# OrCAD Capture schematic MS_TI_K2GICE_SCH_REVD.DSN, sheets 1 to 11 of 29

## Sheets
1 P01_Title Page: title: TABLE OF CONTENTS; rev: D; note: MS_TI_K2GICE_SCH_REVD
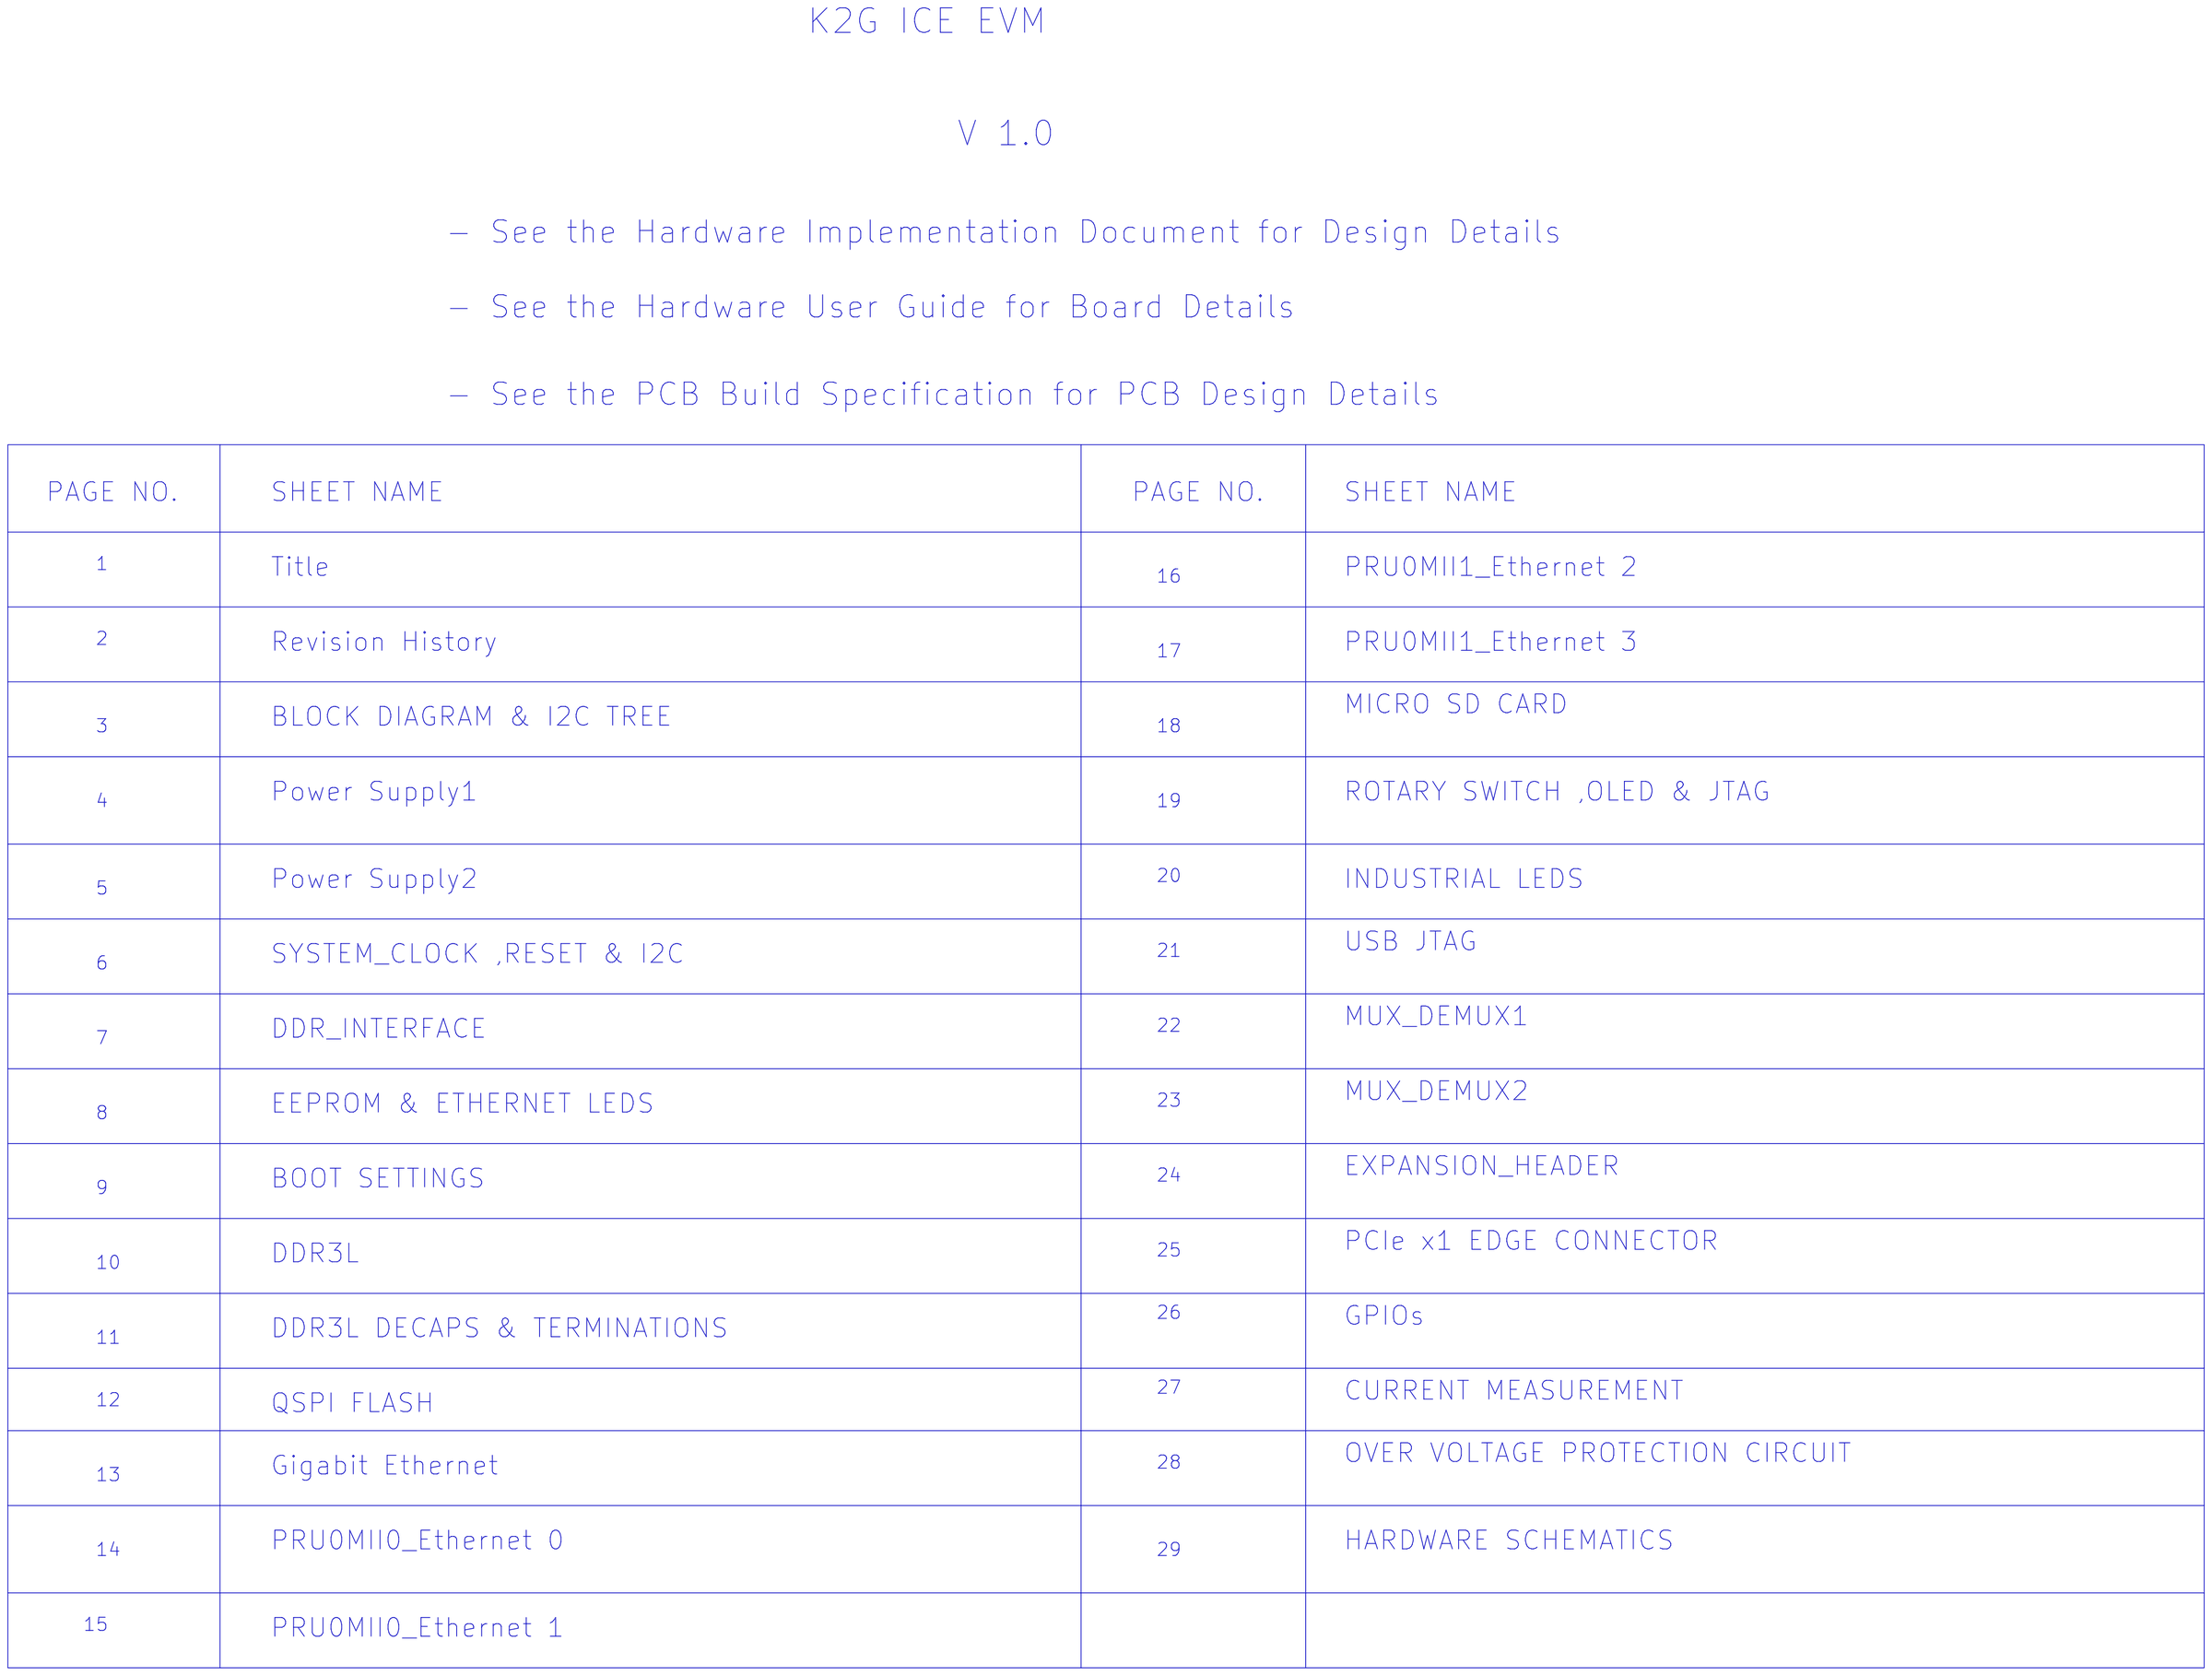
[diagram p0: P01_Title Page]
2 P02_Revision History: title: REVISION HISTORY
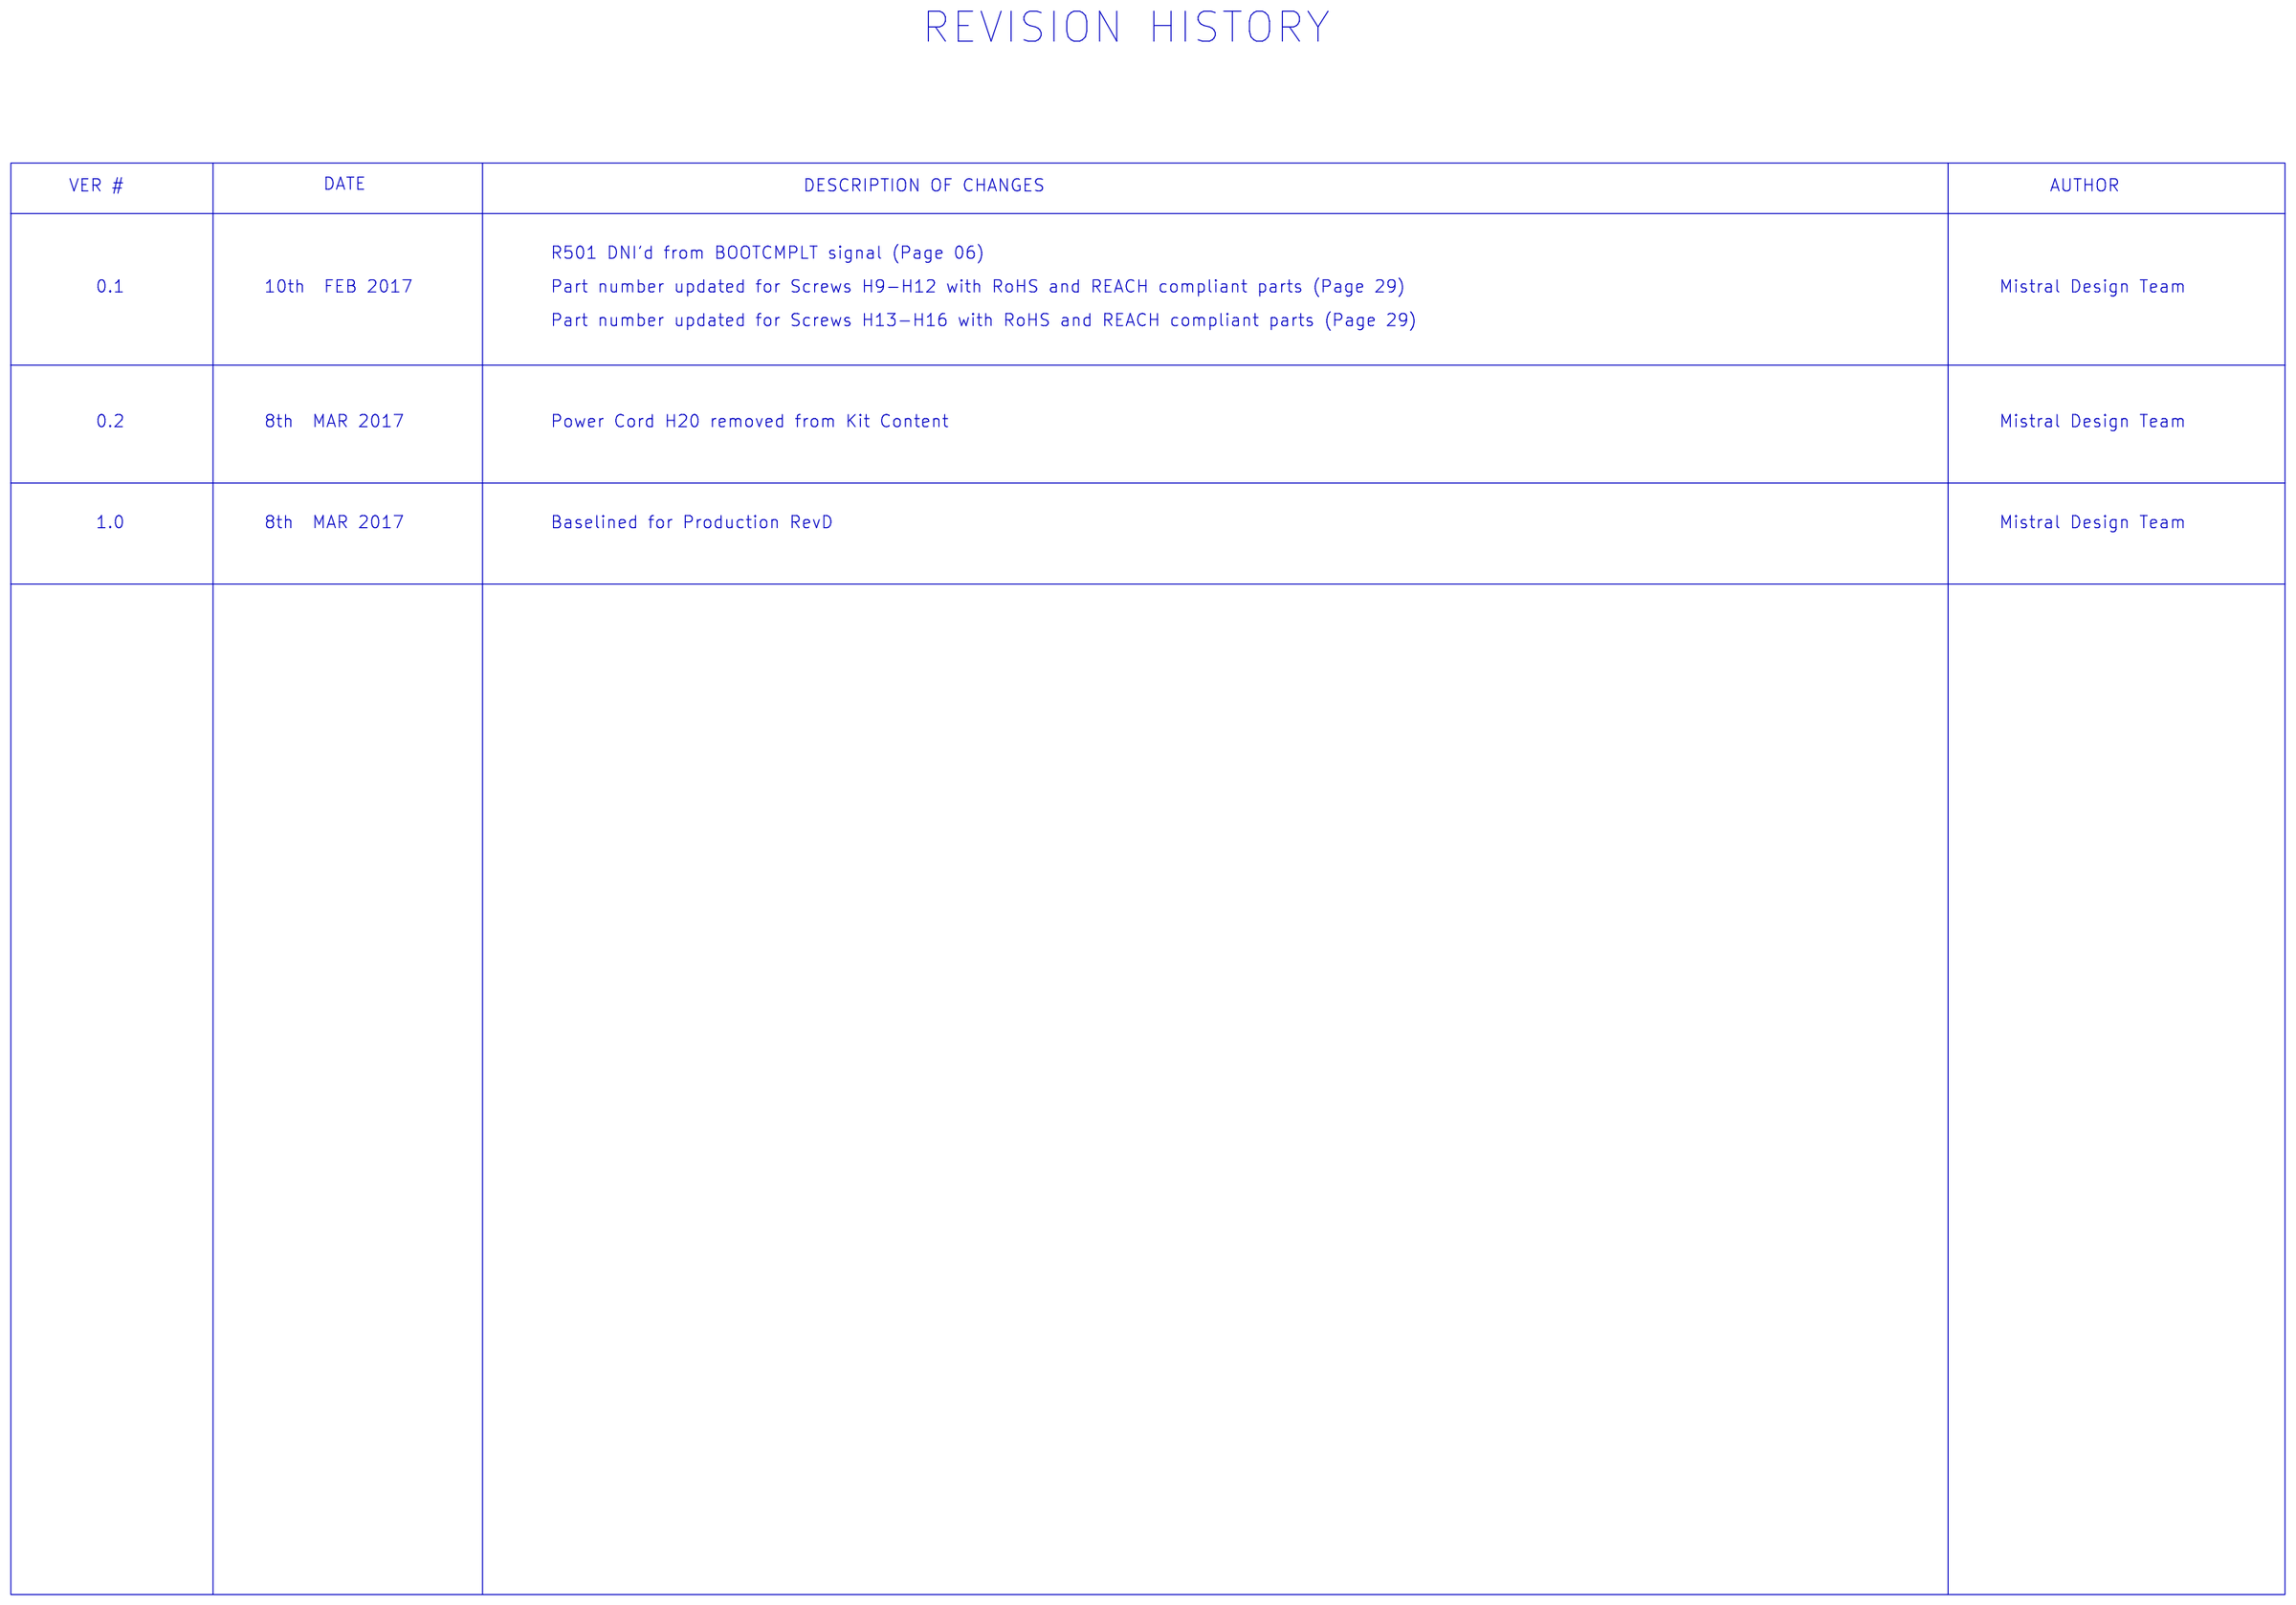
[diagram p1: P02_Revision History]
3 P03_BLOCK DIAGRAM & I2C TREE: title: BLOCK DIAGRAM & I2C TREE
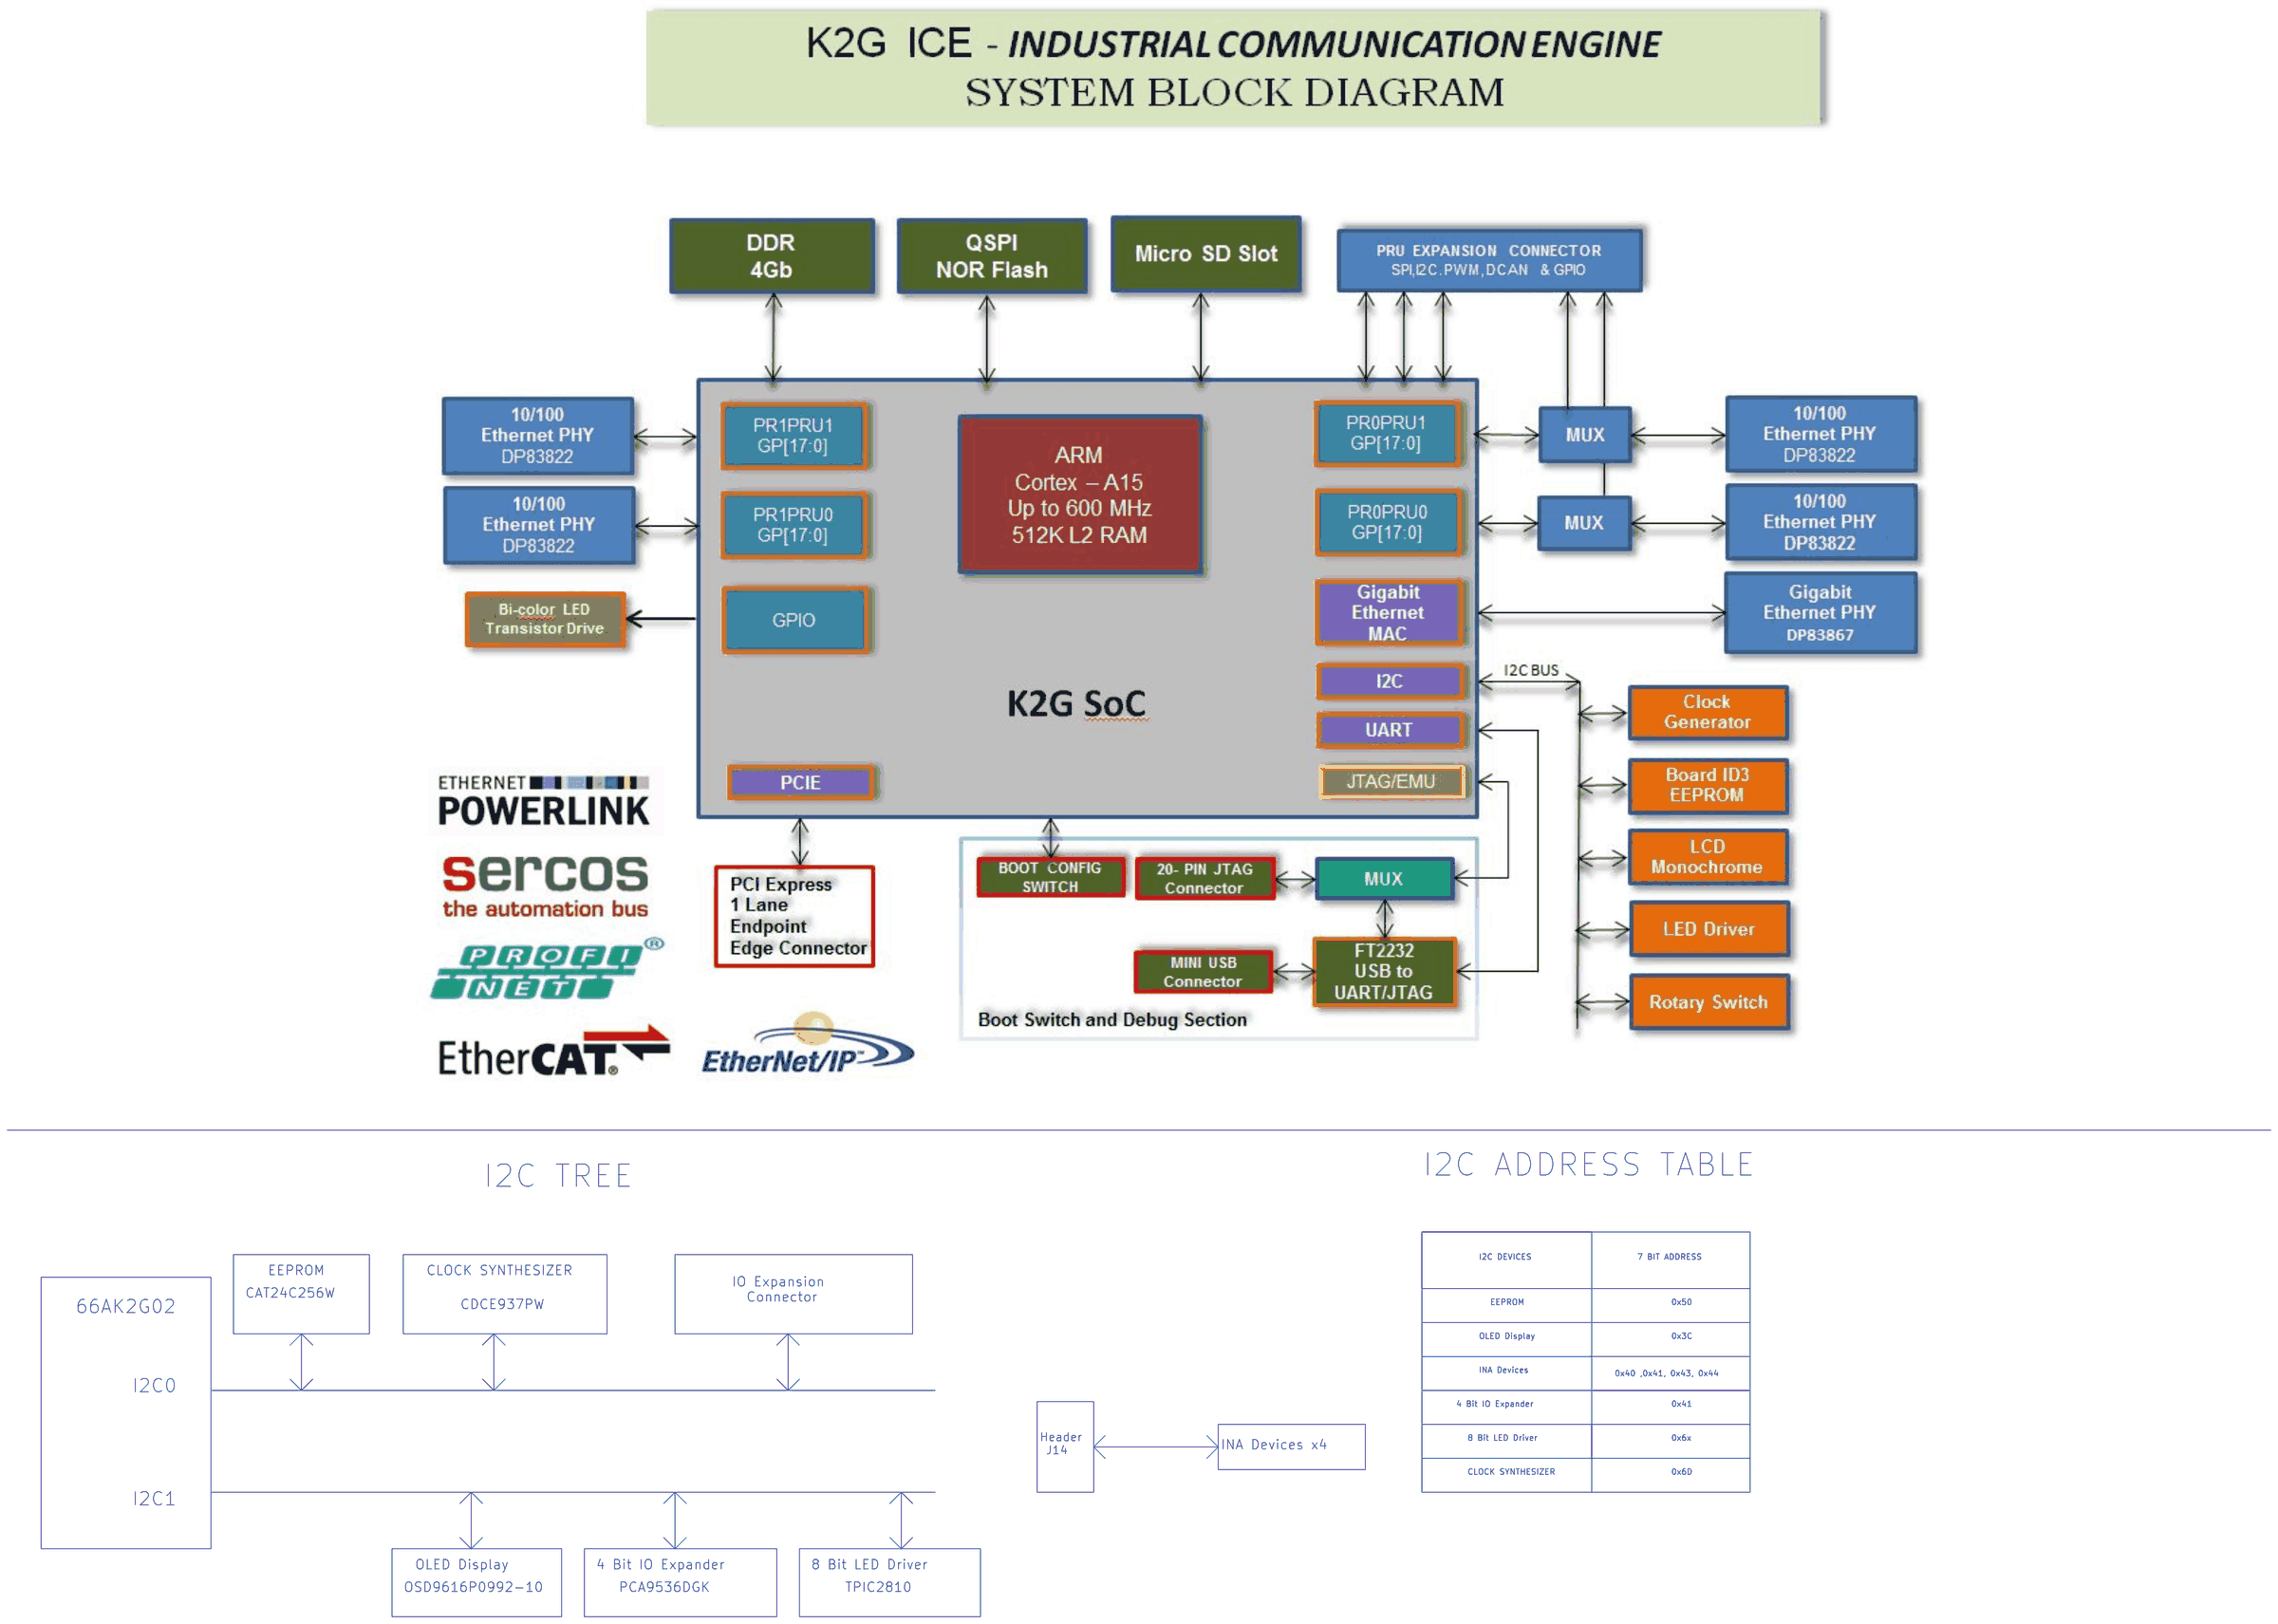
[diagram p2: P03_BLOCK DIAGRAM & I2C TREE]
4 P04_K2G_PowerSupply1: size C; title: POWER SUPPLY 1
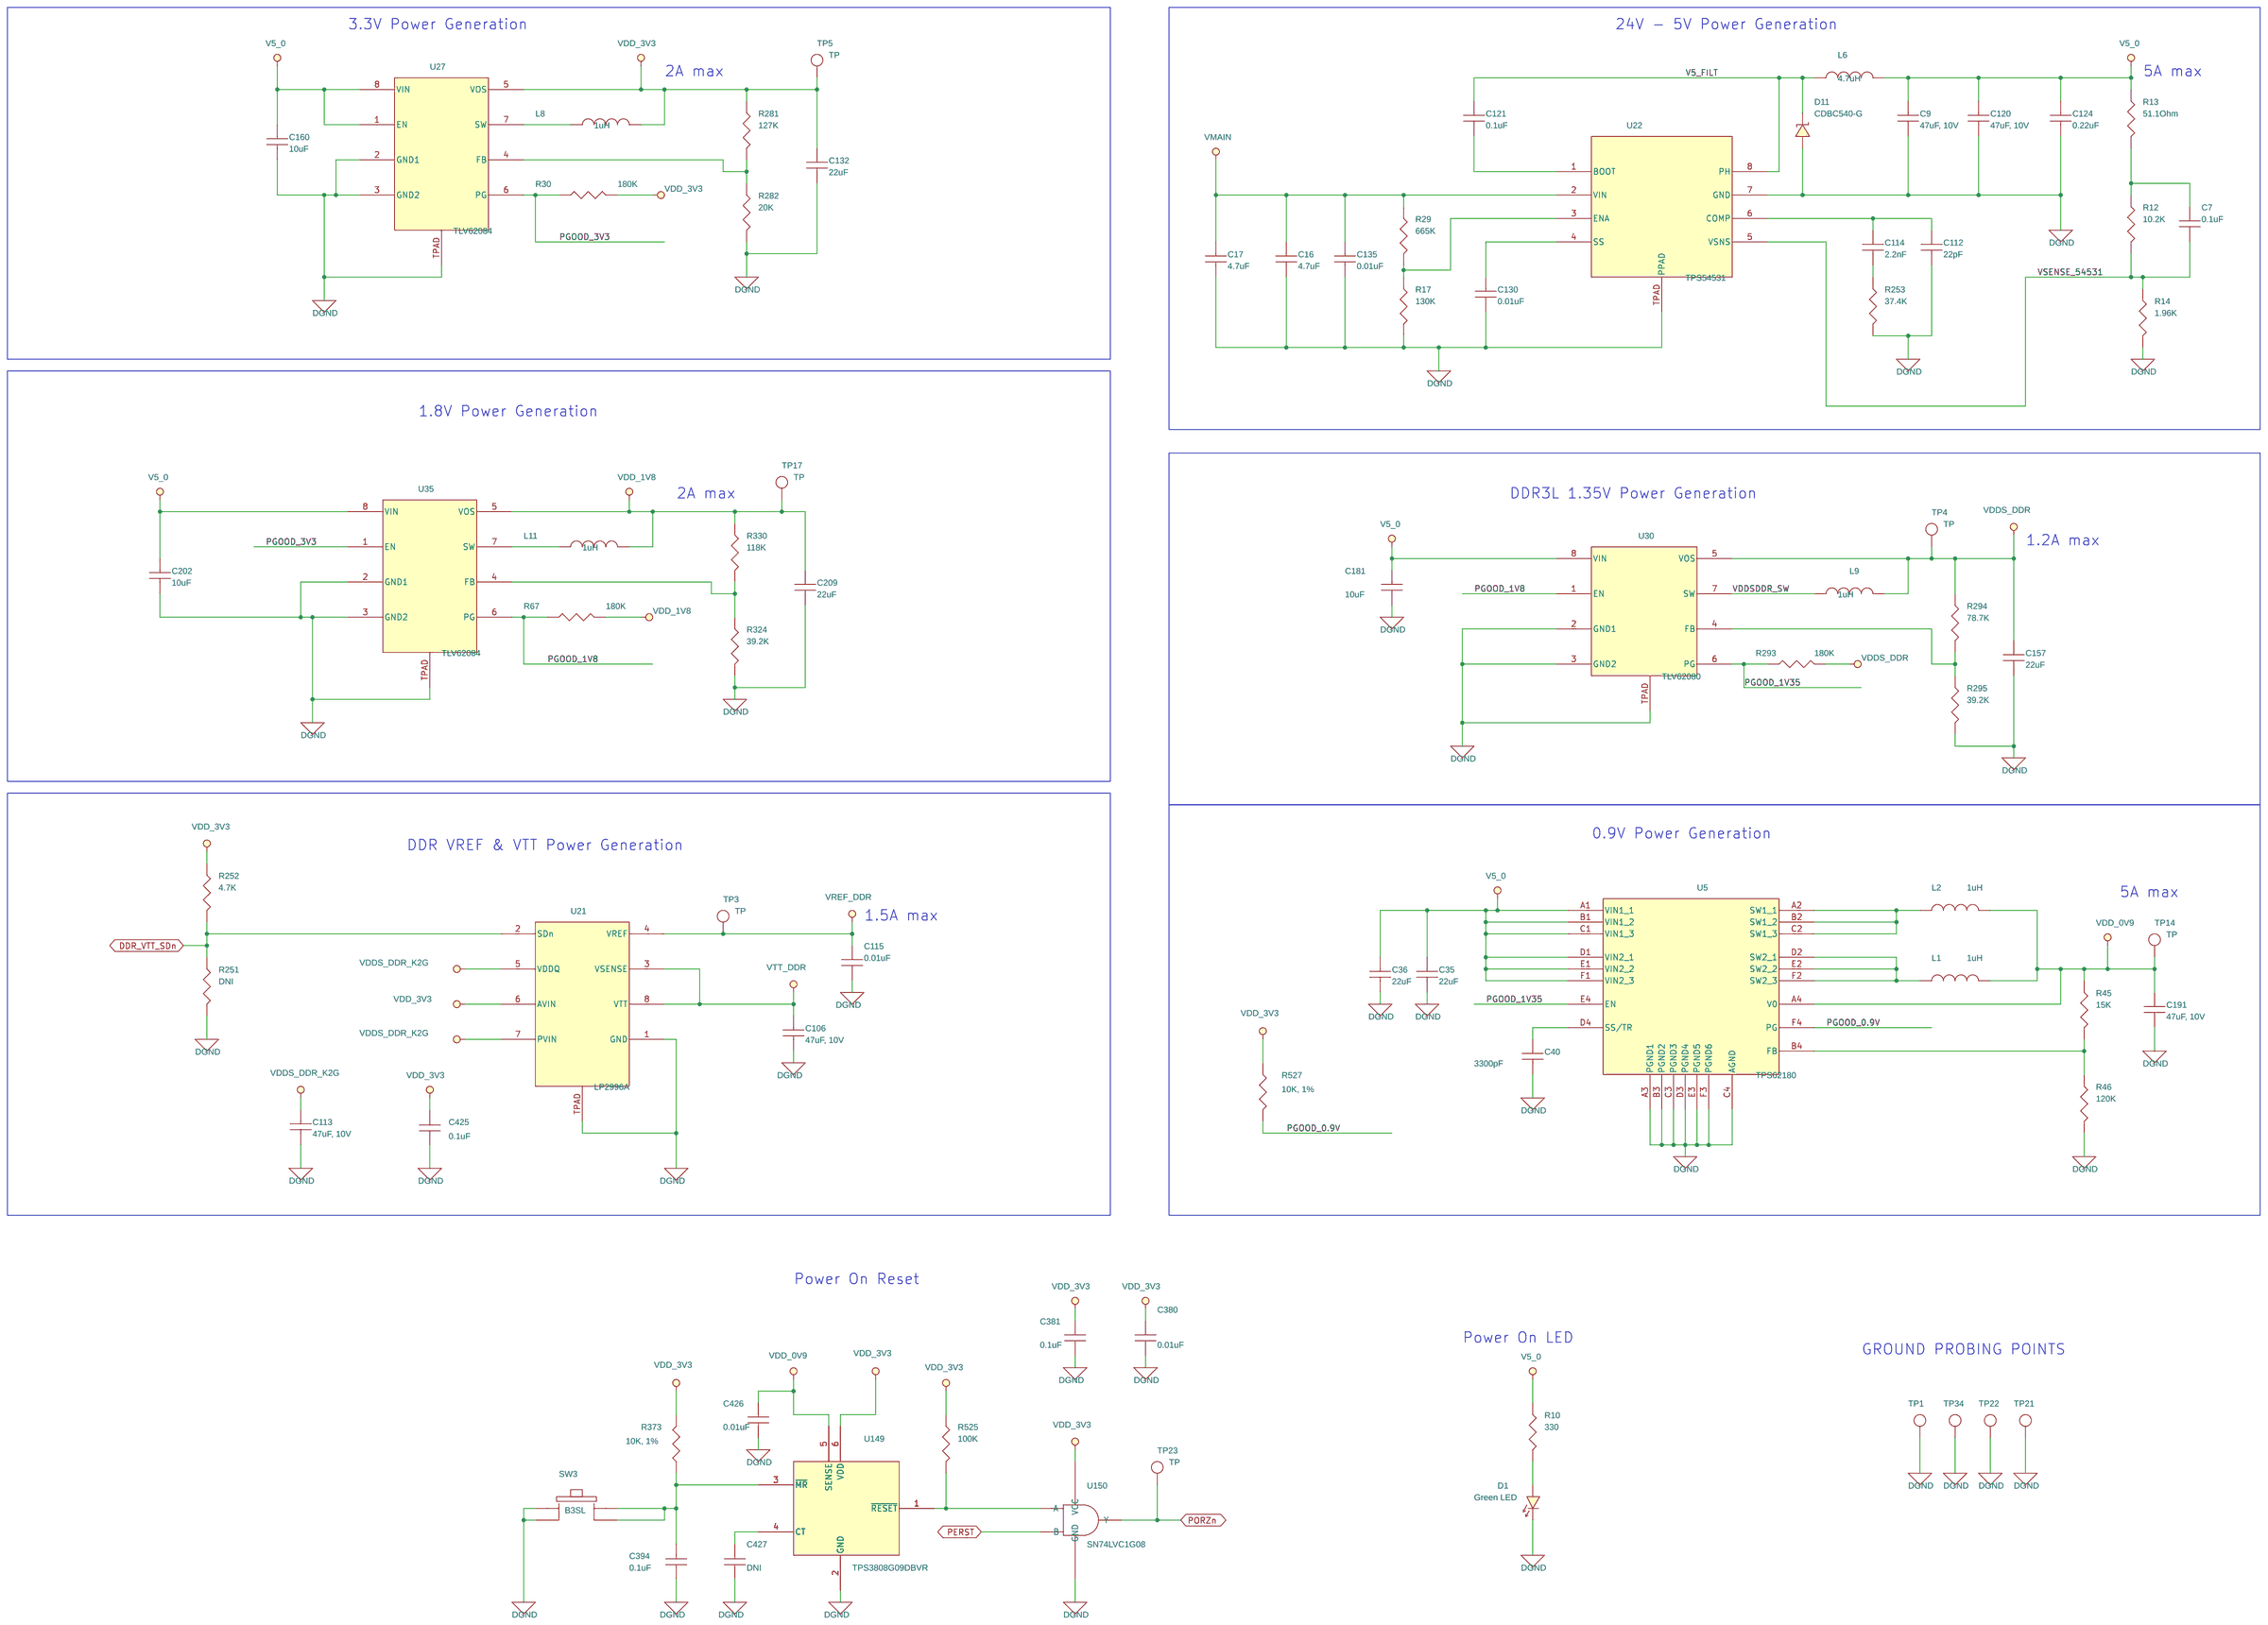
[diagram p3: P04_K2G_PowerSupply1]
5 P05_K2G_Power Supply2: size C; title: POWER SUPPLY 2
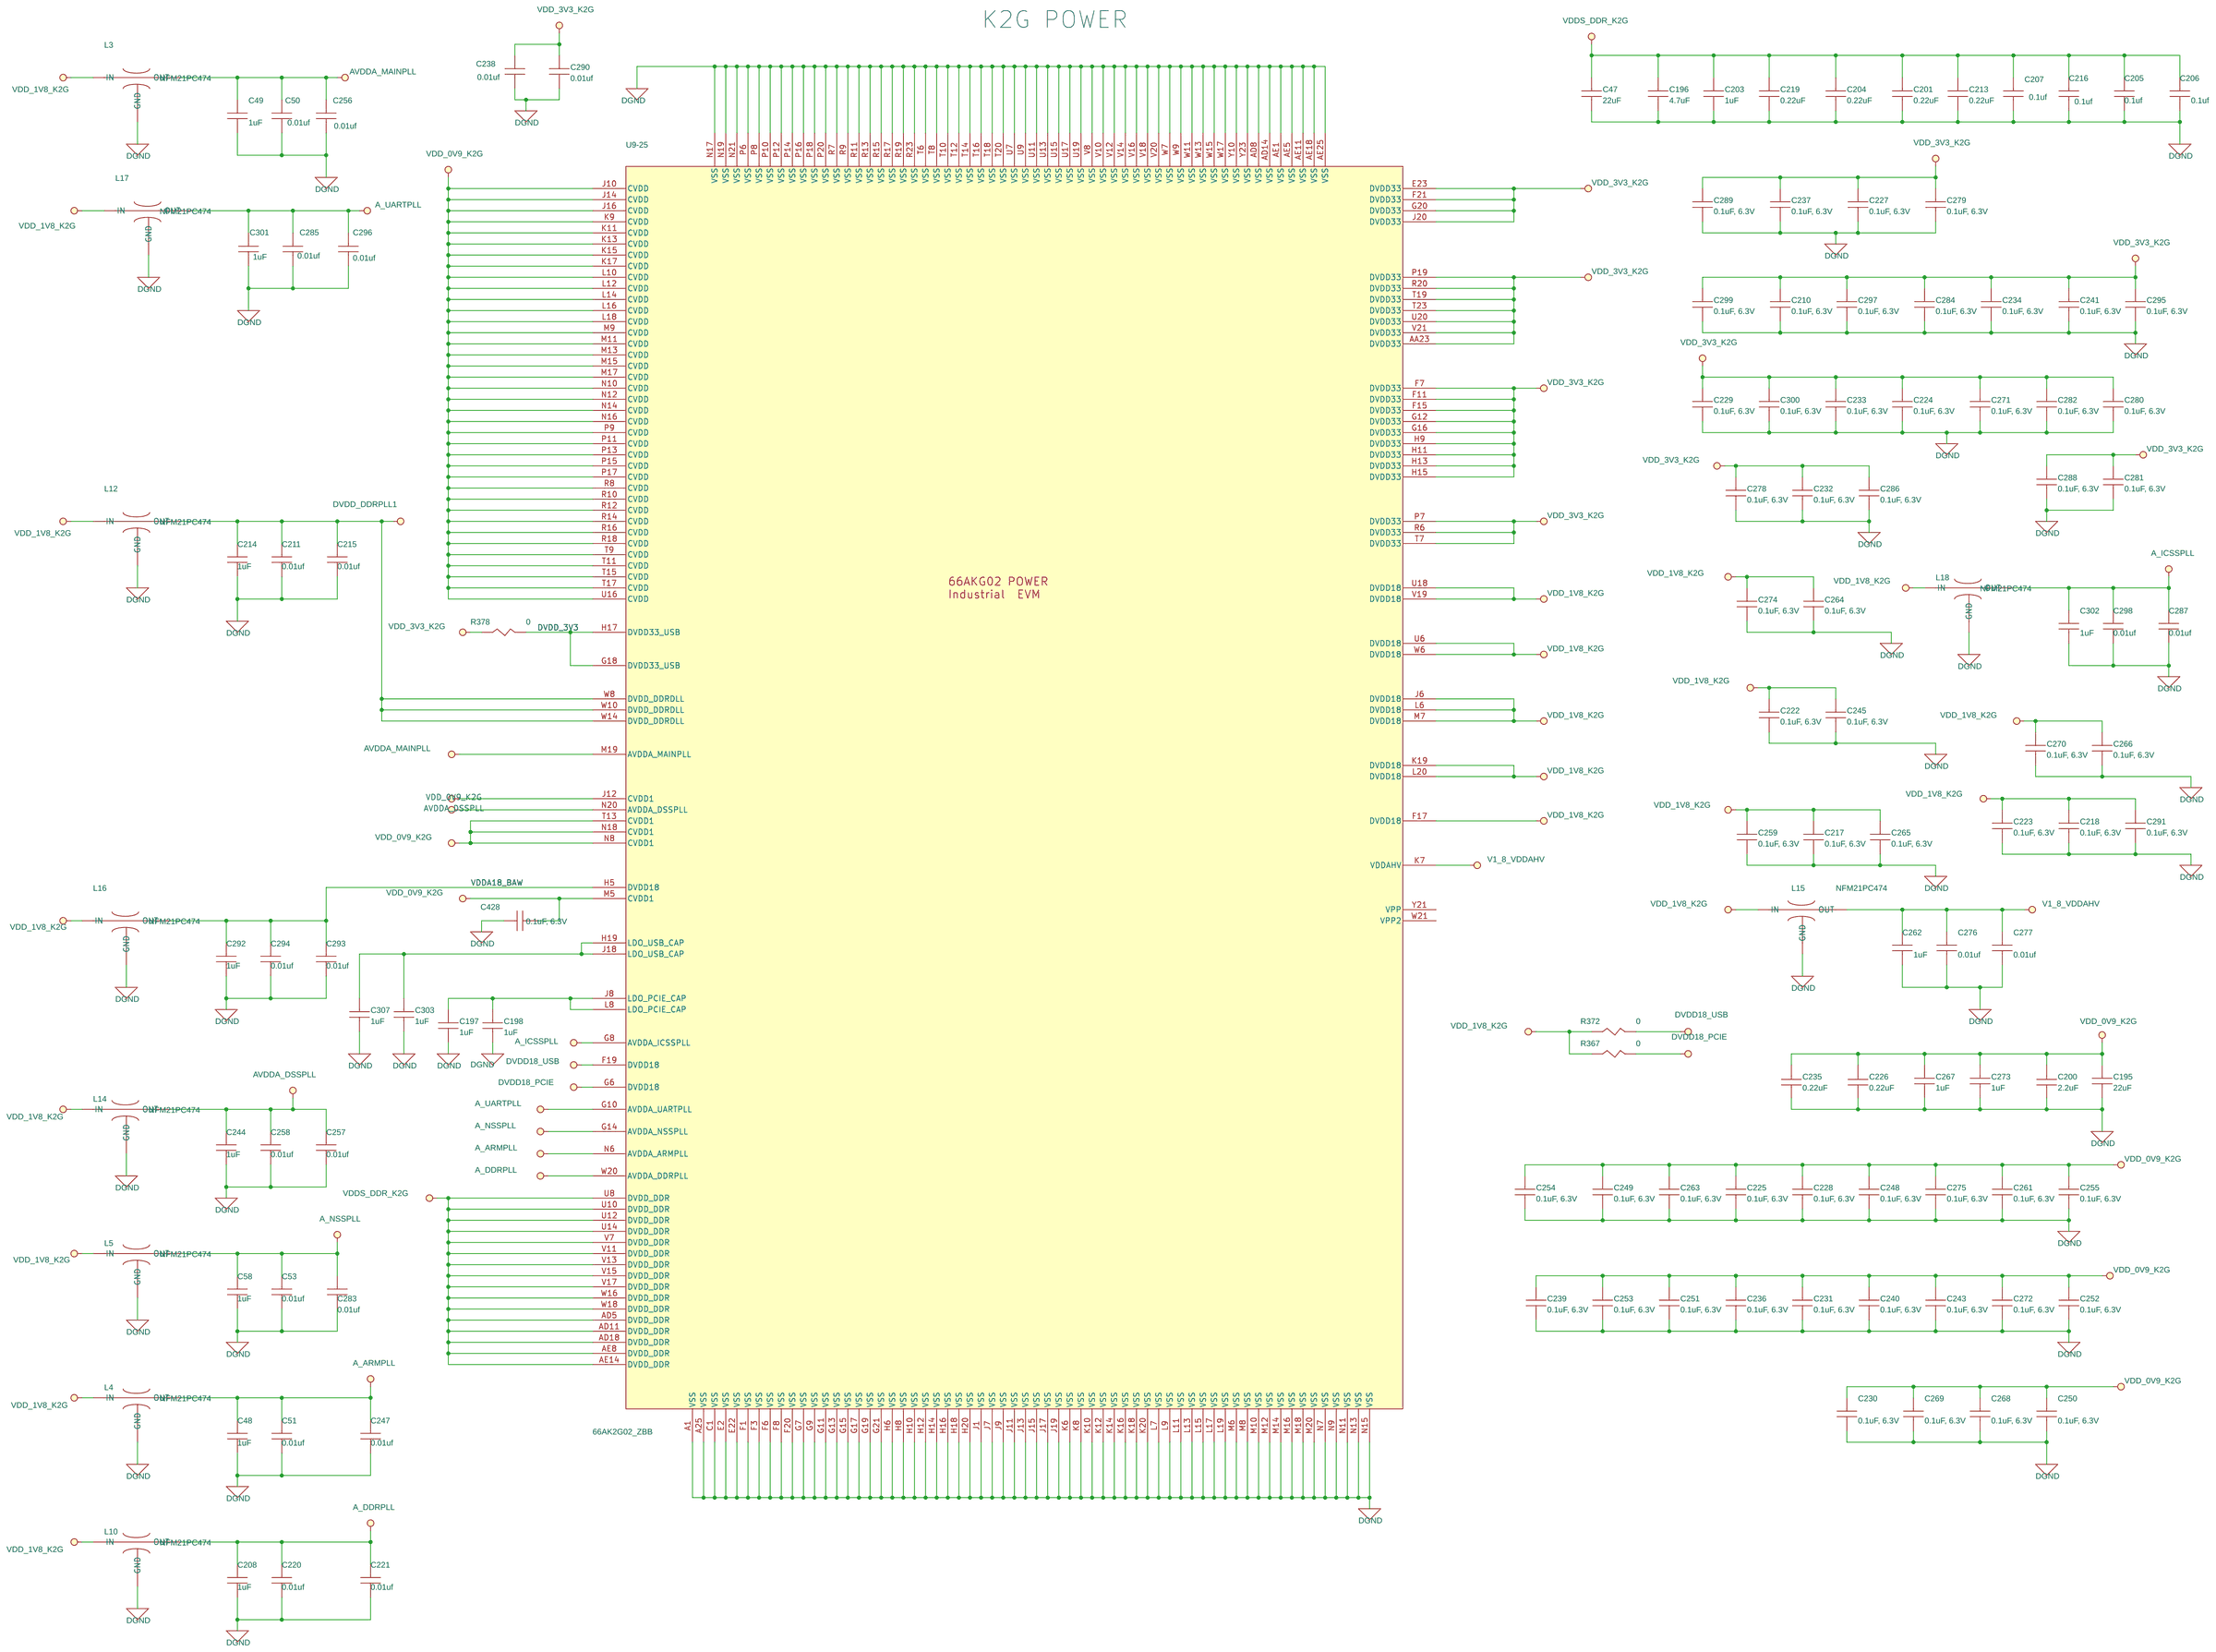
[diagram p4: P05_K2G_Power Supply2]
6 P06_K2G_SYSTEM_CLOCK_RESET_I2C: size C; title: SYSTEM_CLOCK_RESET_I2C
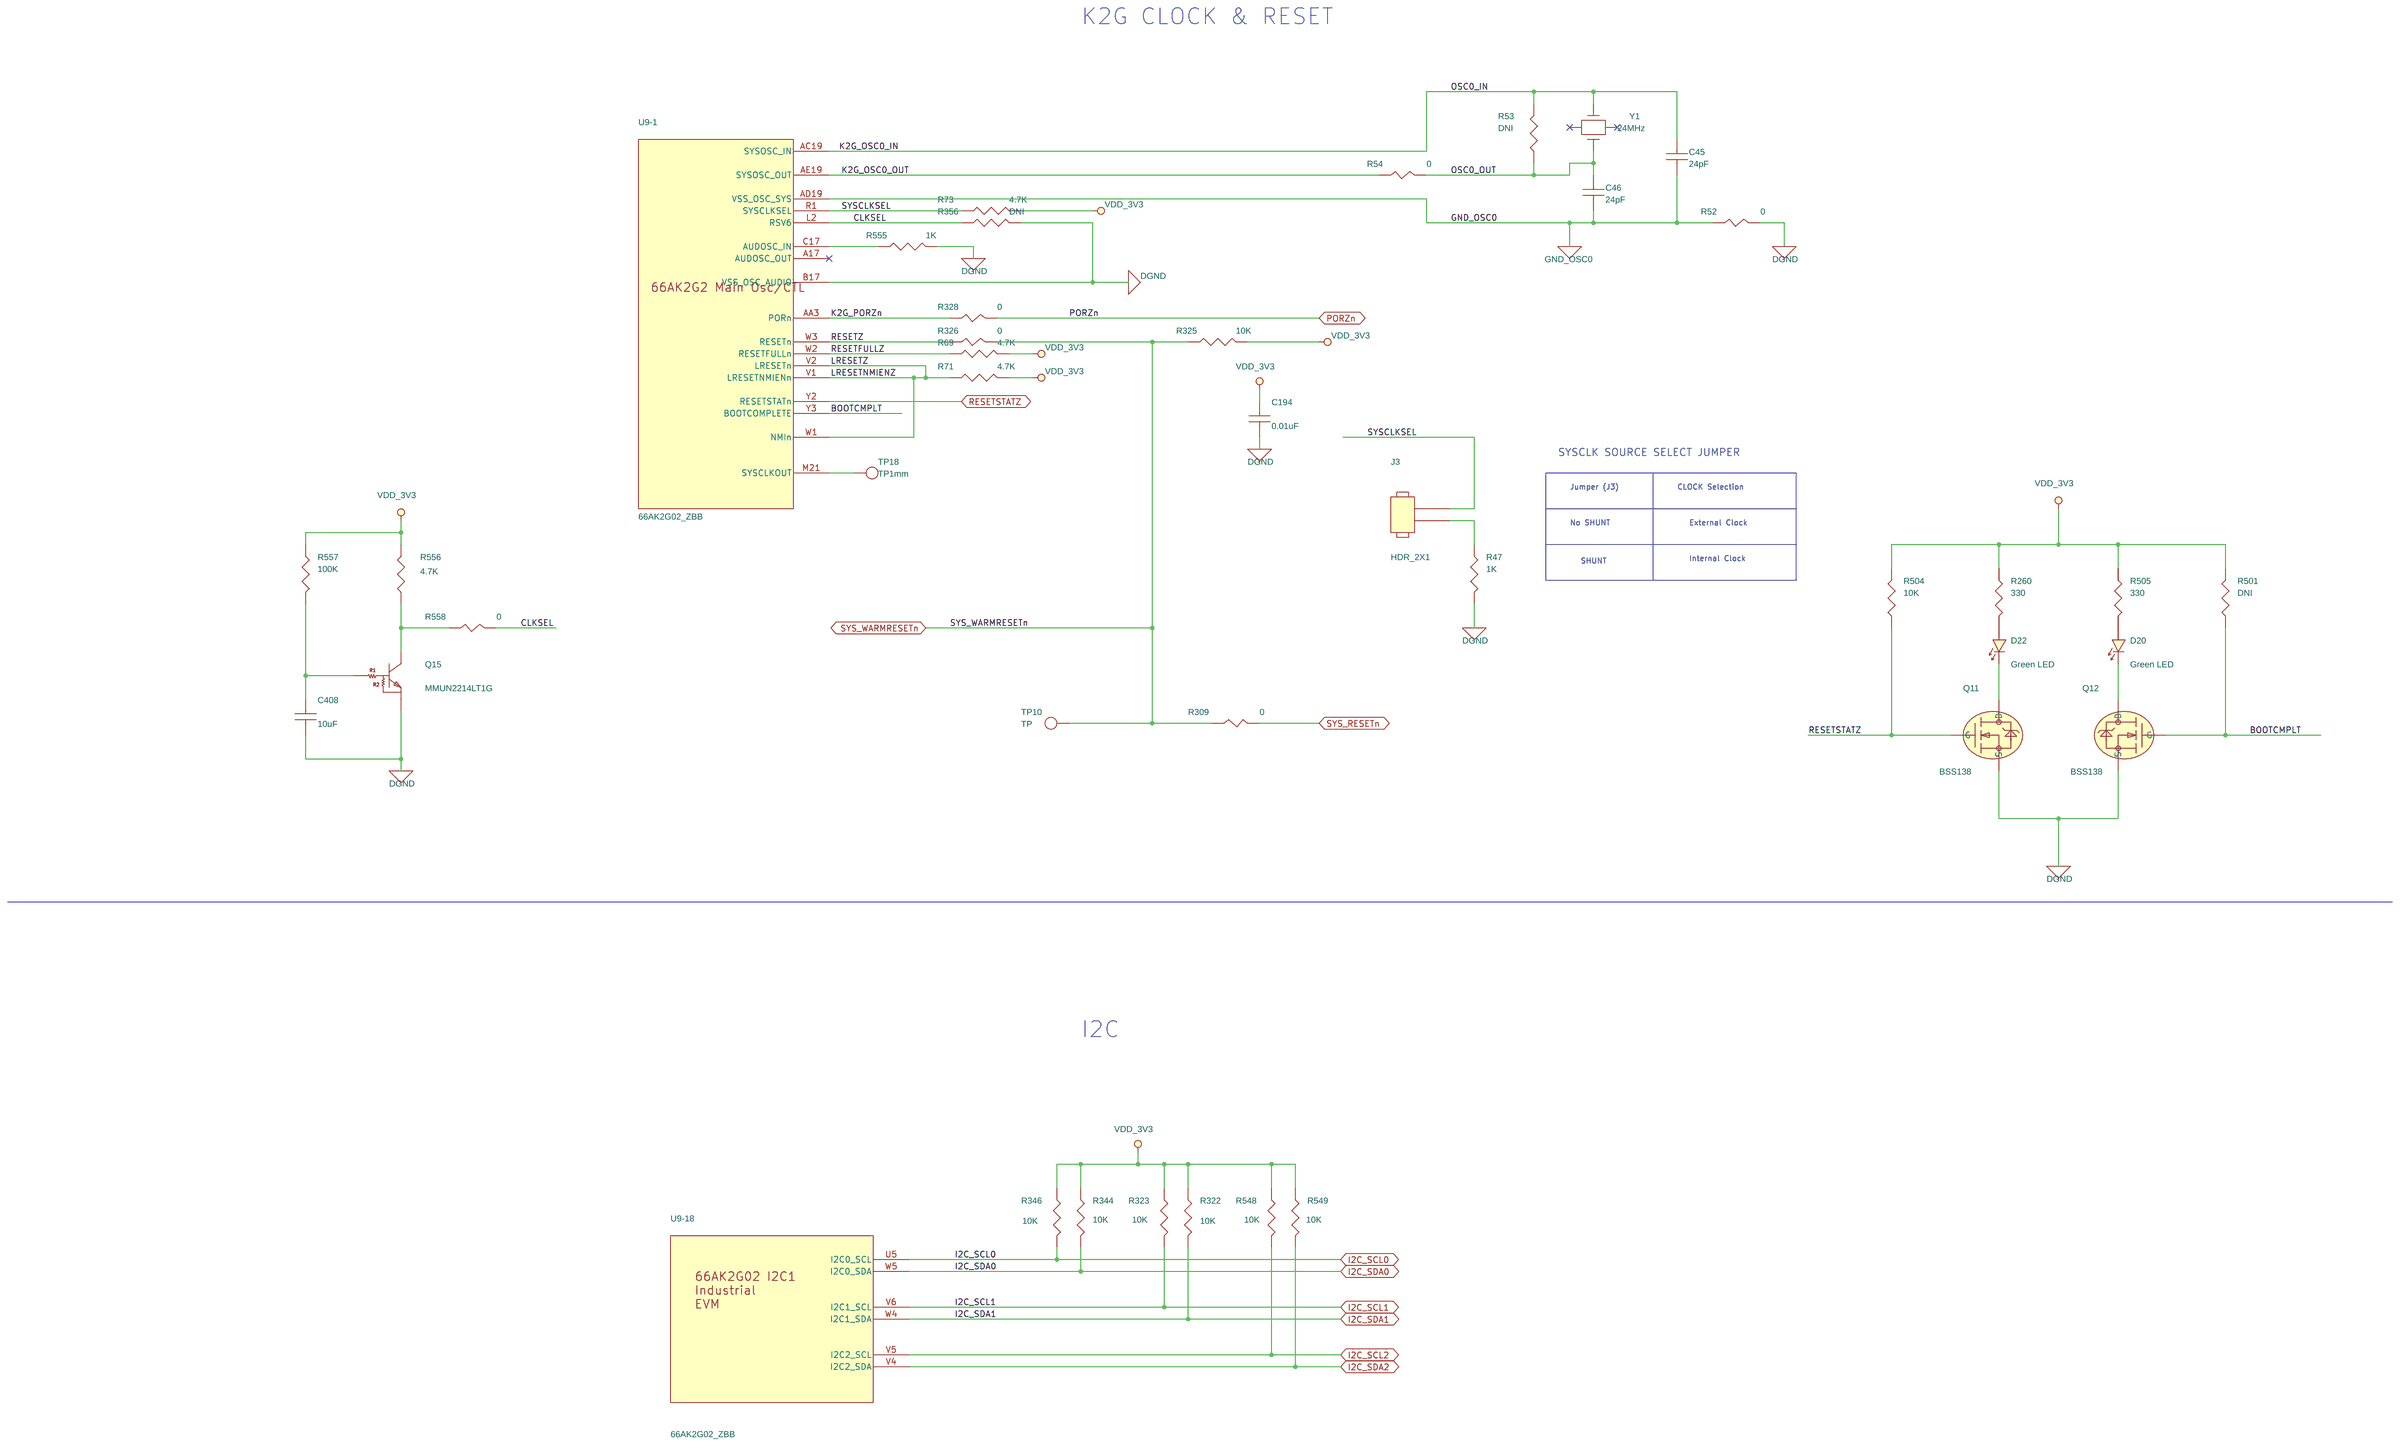
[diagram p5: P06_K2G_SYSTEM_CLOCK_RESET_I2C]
7 P07_K2G_ICE_DDR3L_INTERFACE: size C; title: DDR_INTERFACE
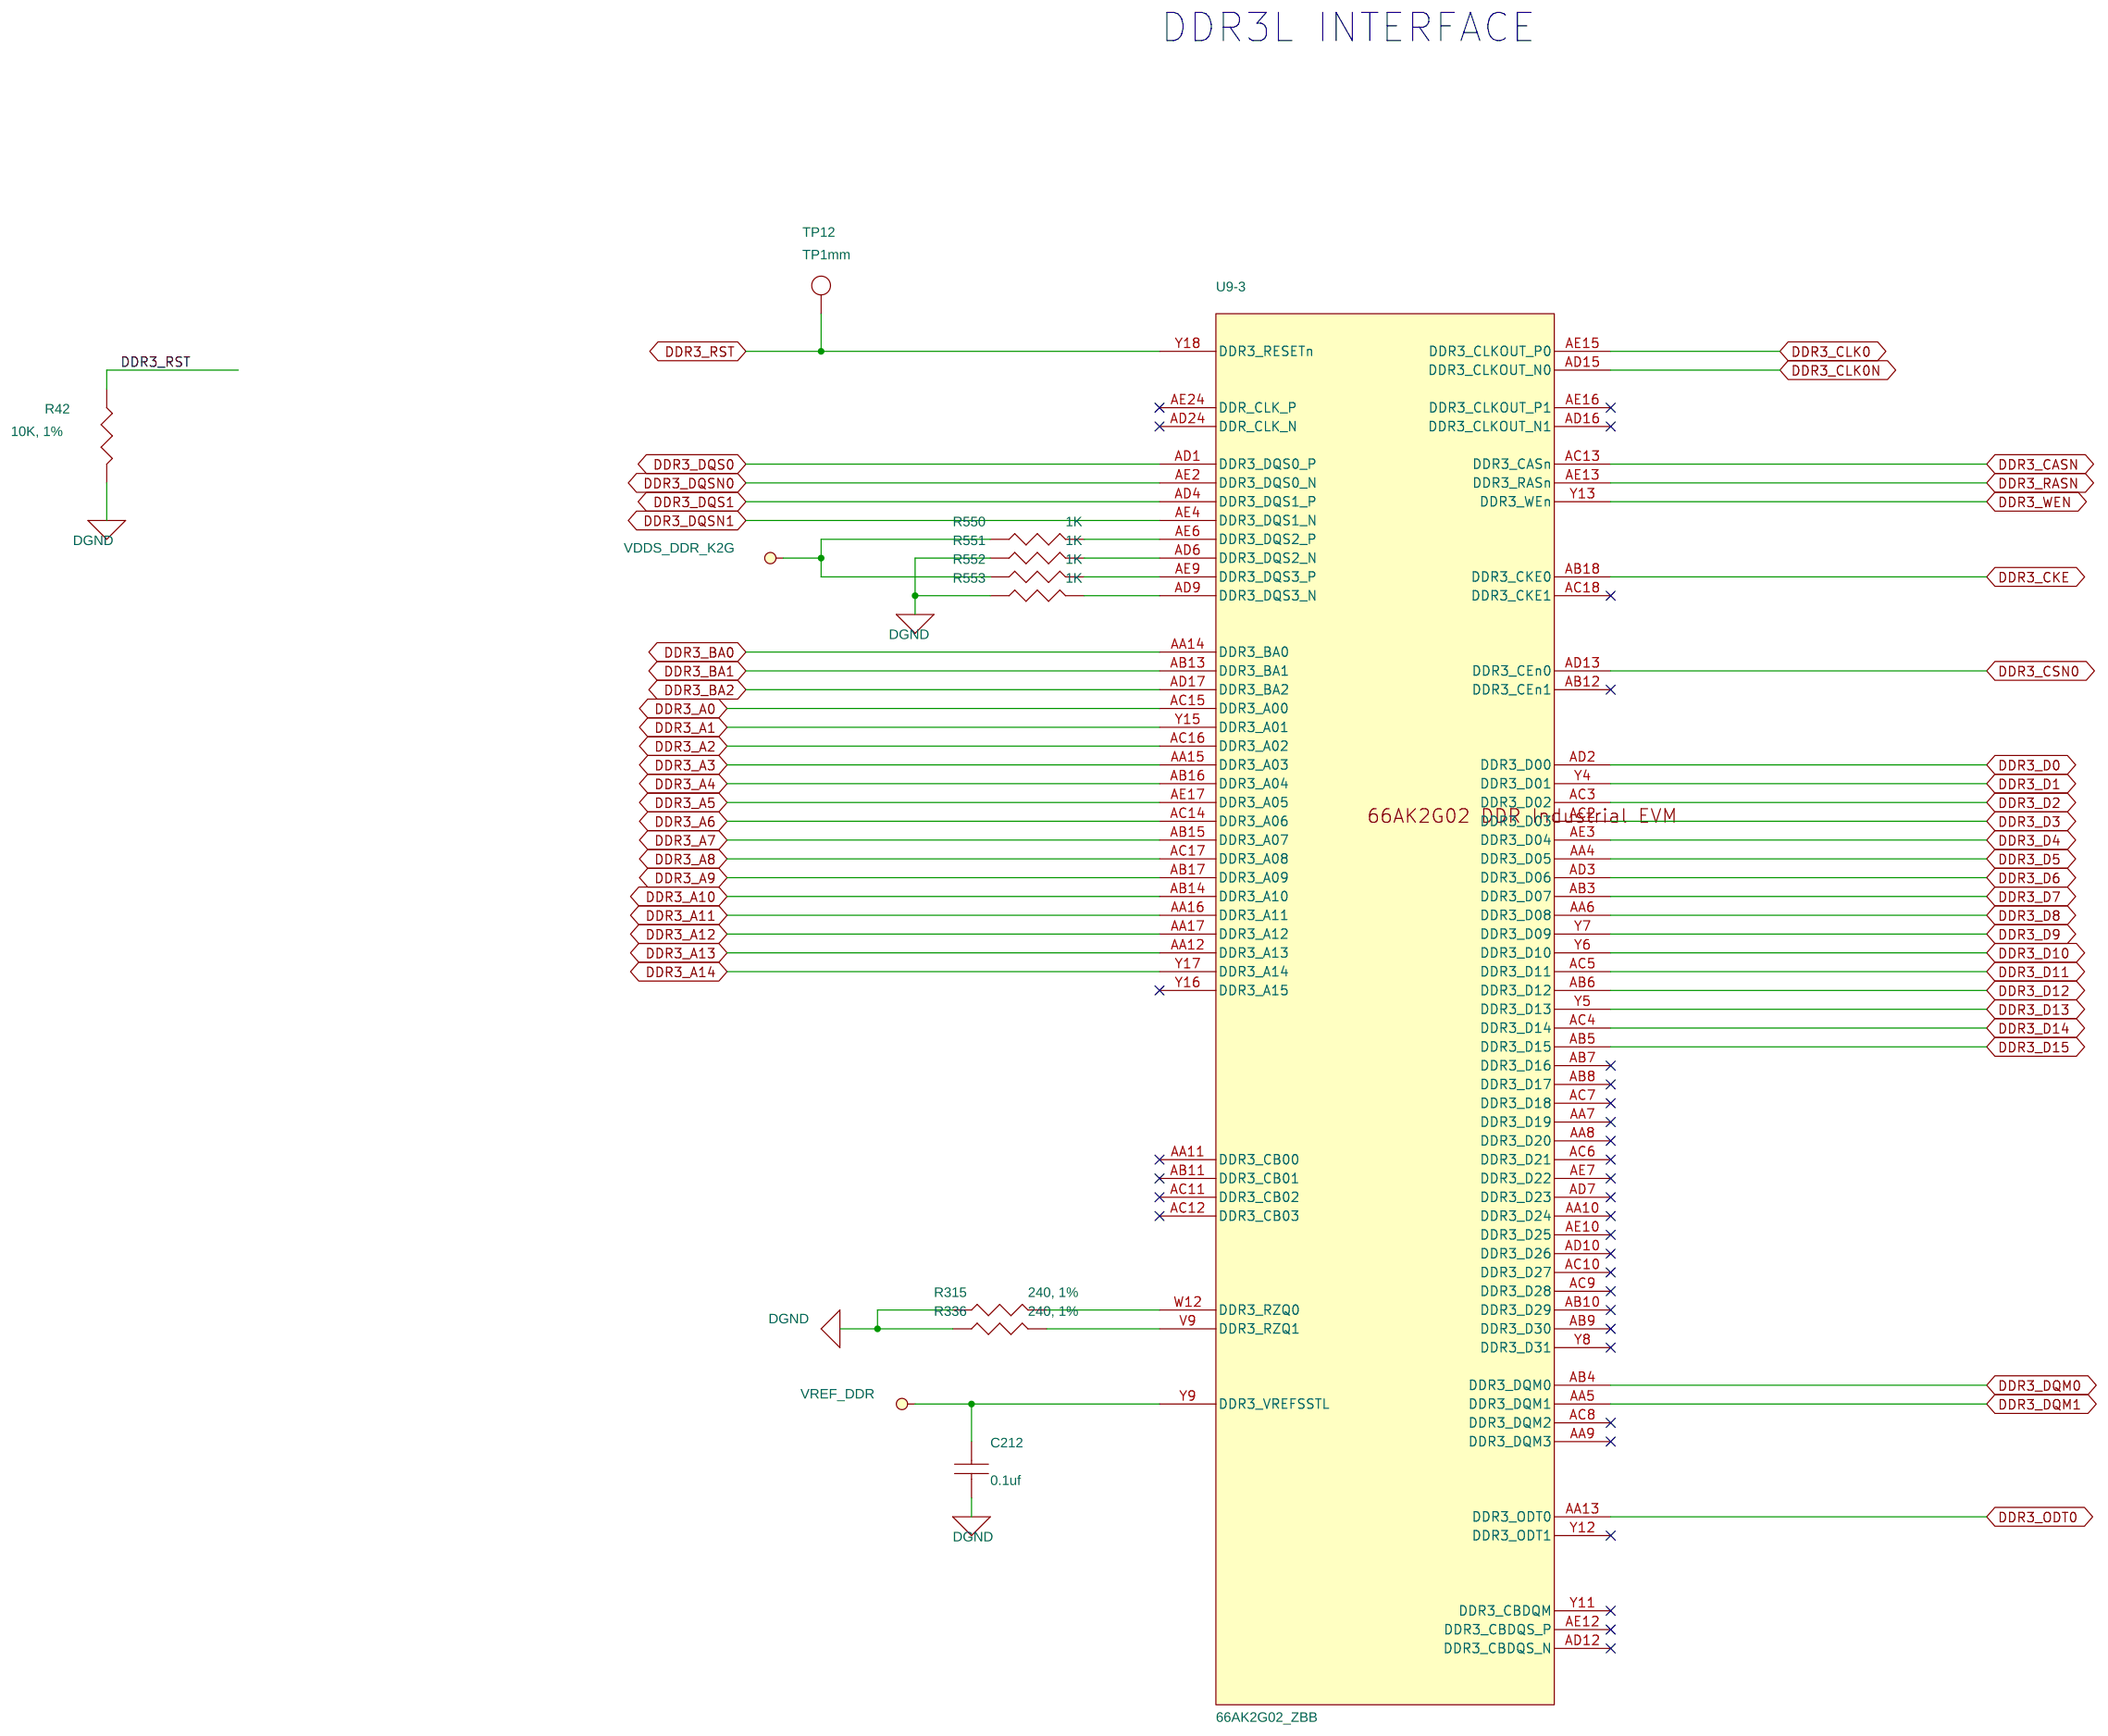
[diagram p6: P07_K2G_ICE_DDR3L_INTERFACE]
8 P08_K2G_ICE_EEPROM_ETHERNETLEDS: size C; title: EEPROM_ETHERNETLEDS
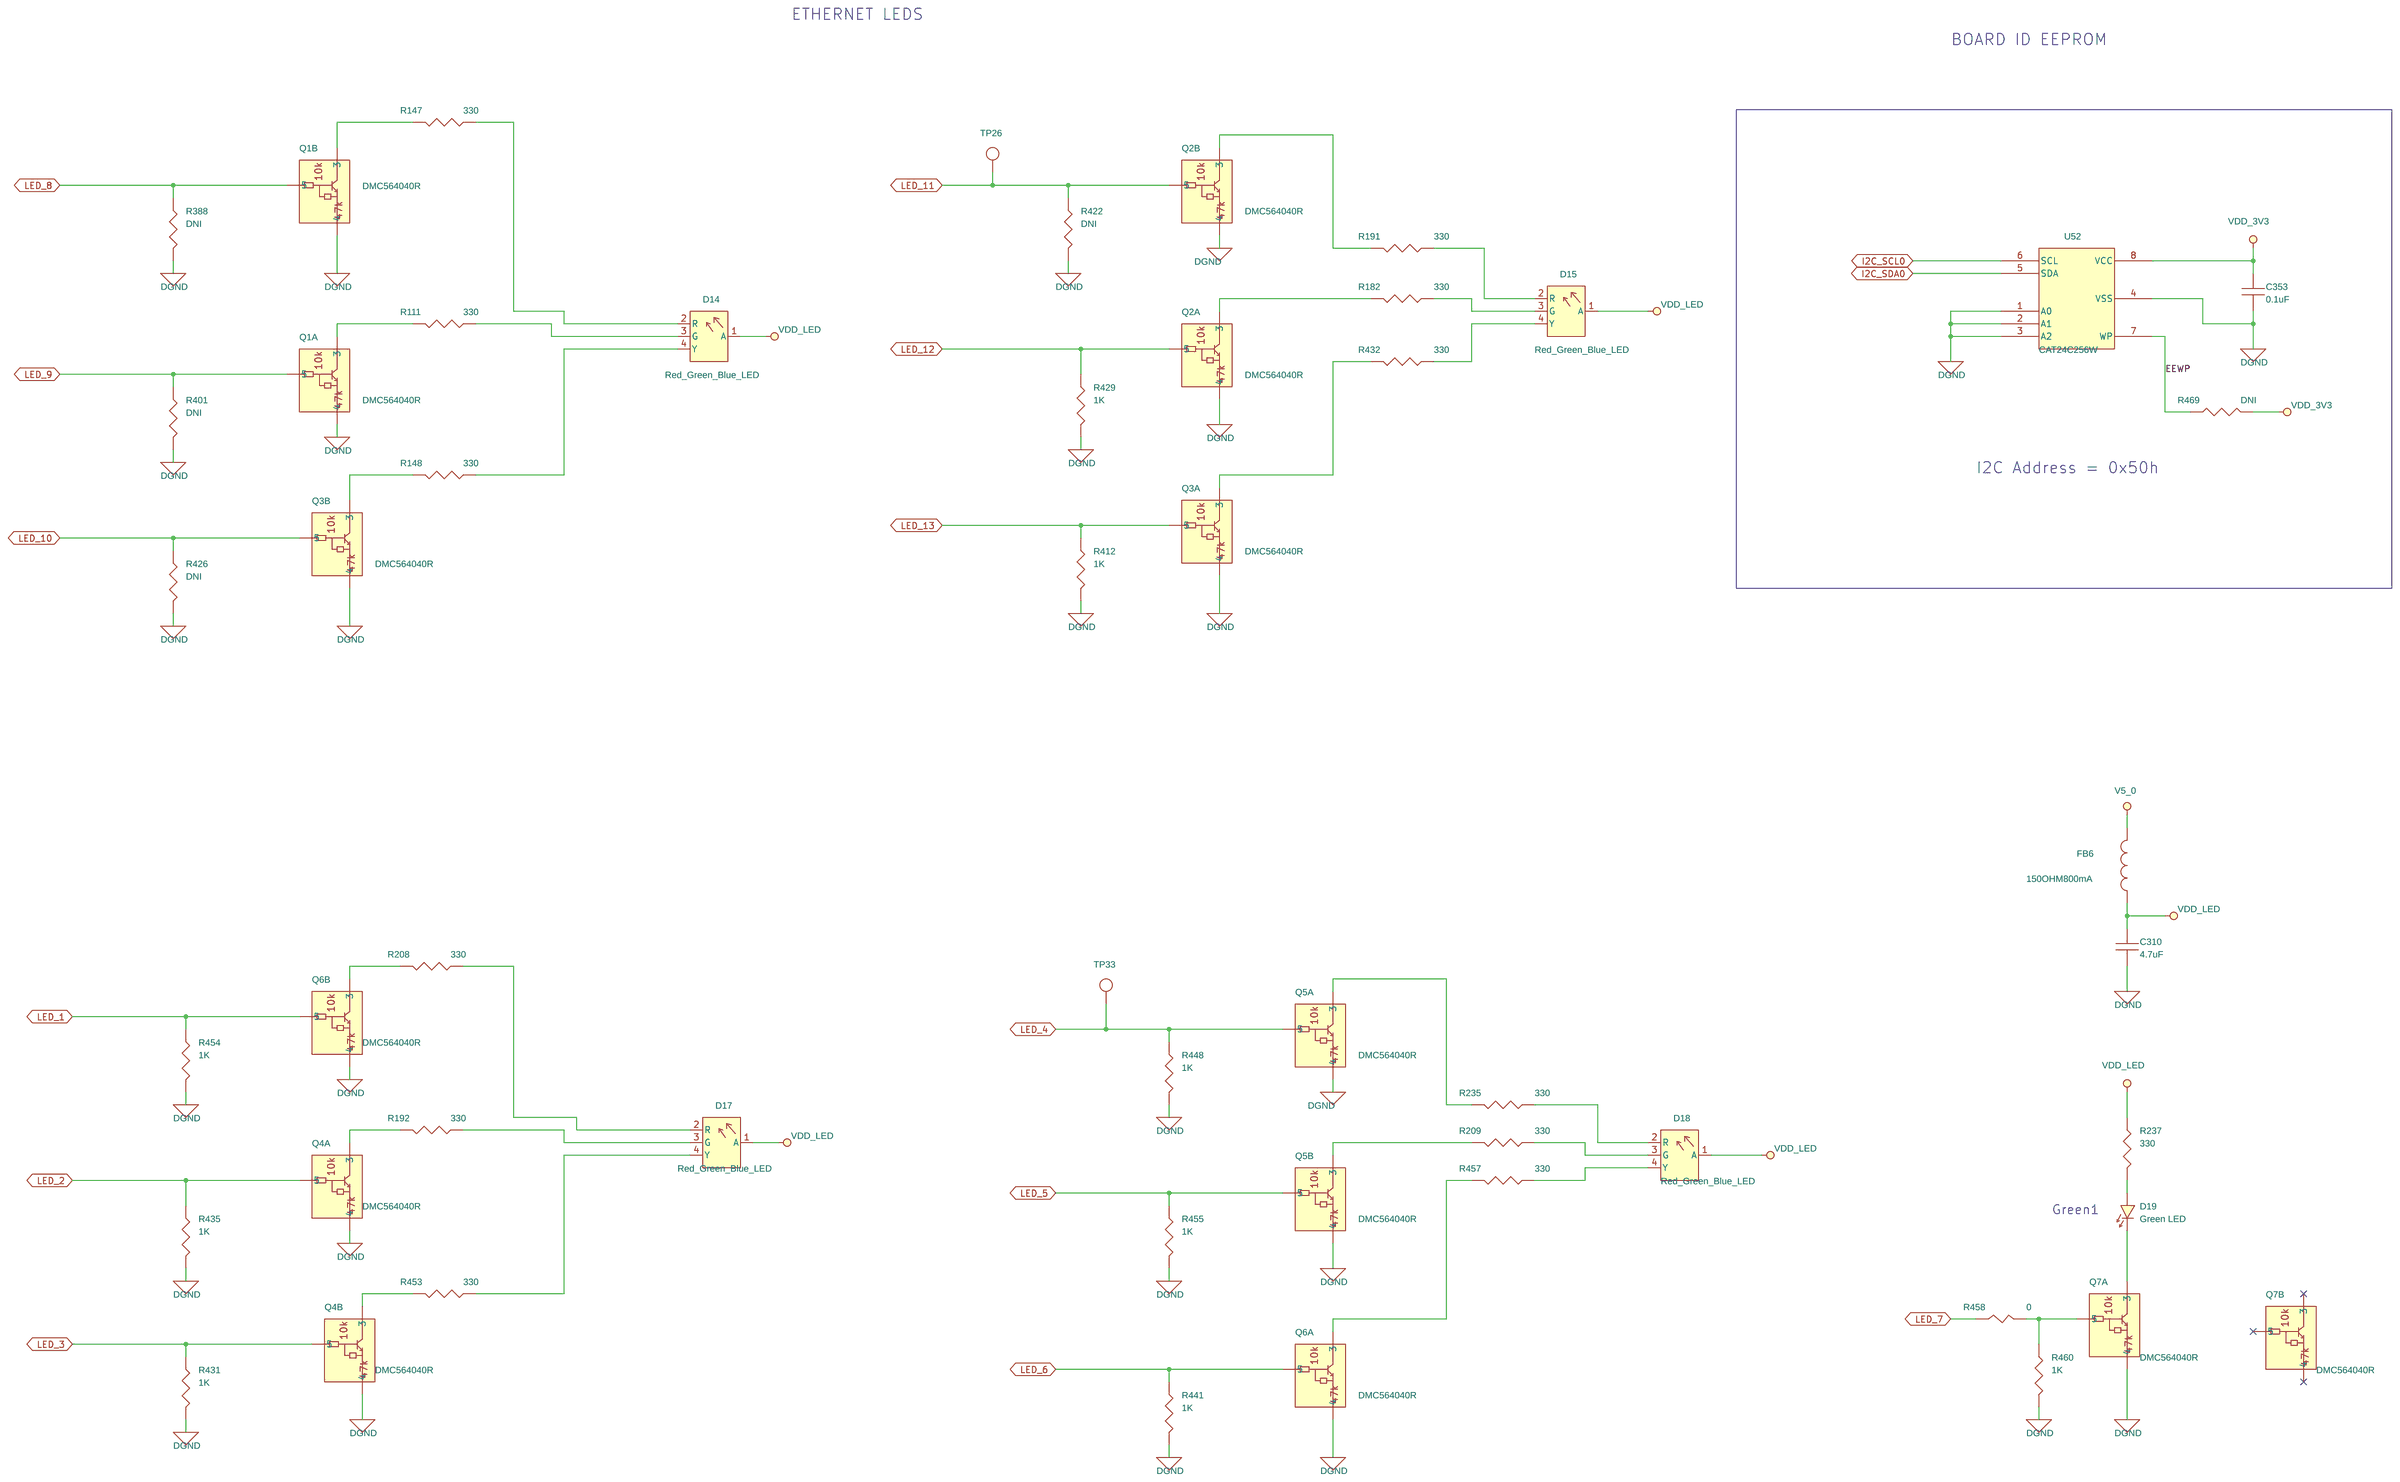
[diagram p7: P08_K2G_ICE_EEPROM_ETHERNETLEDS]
9 P09_K2G_ICE_BOOT: size C; title: BOOT SETTINGS
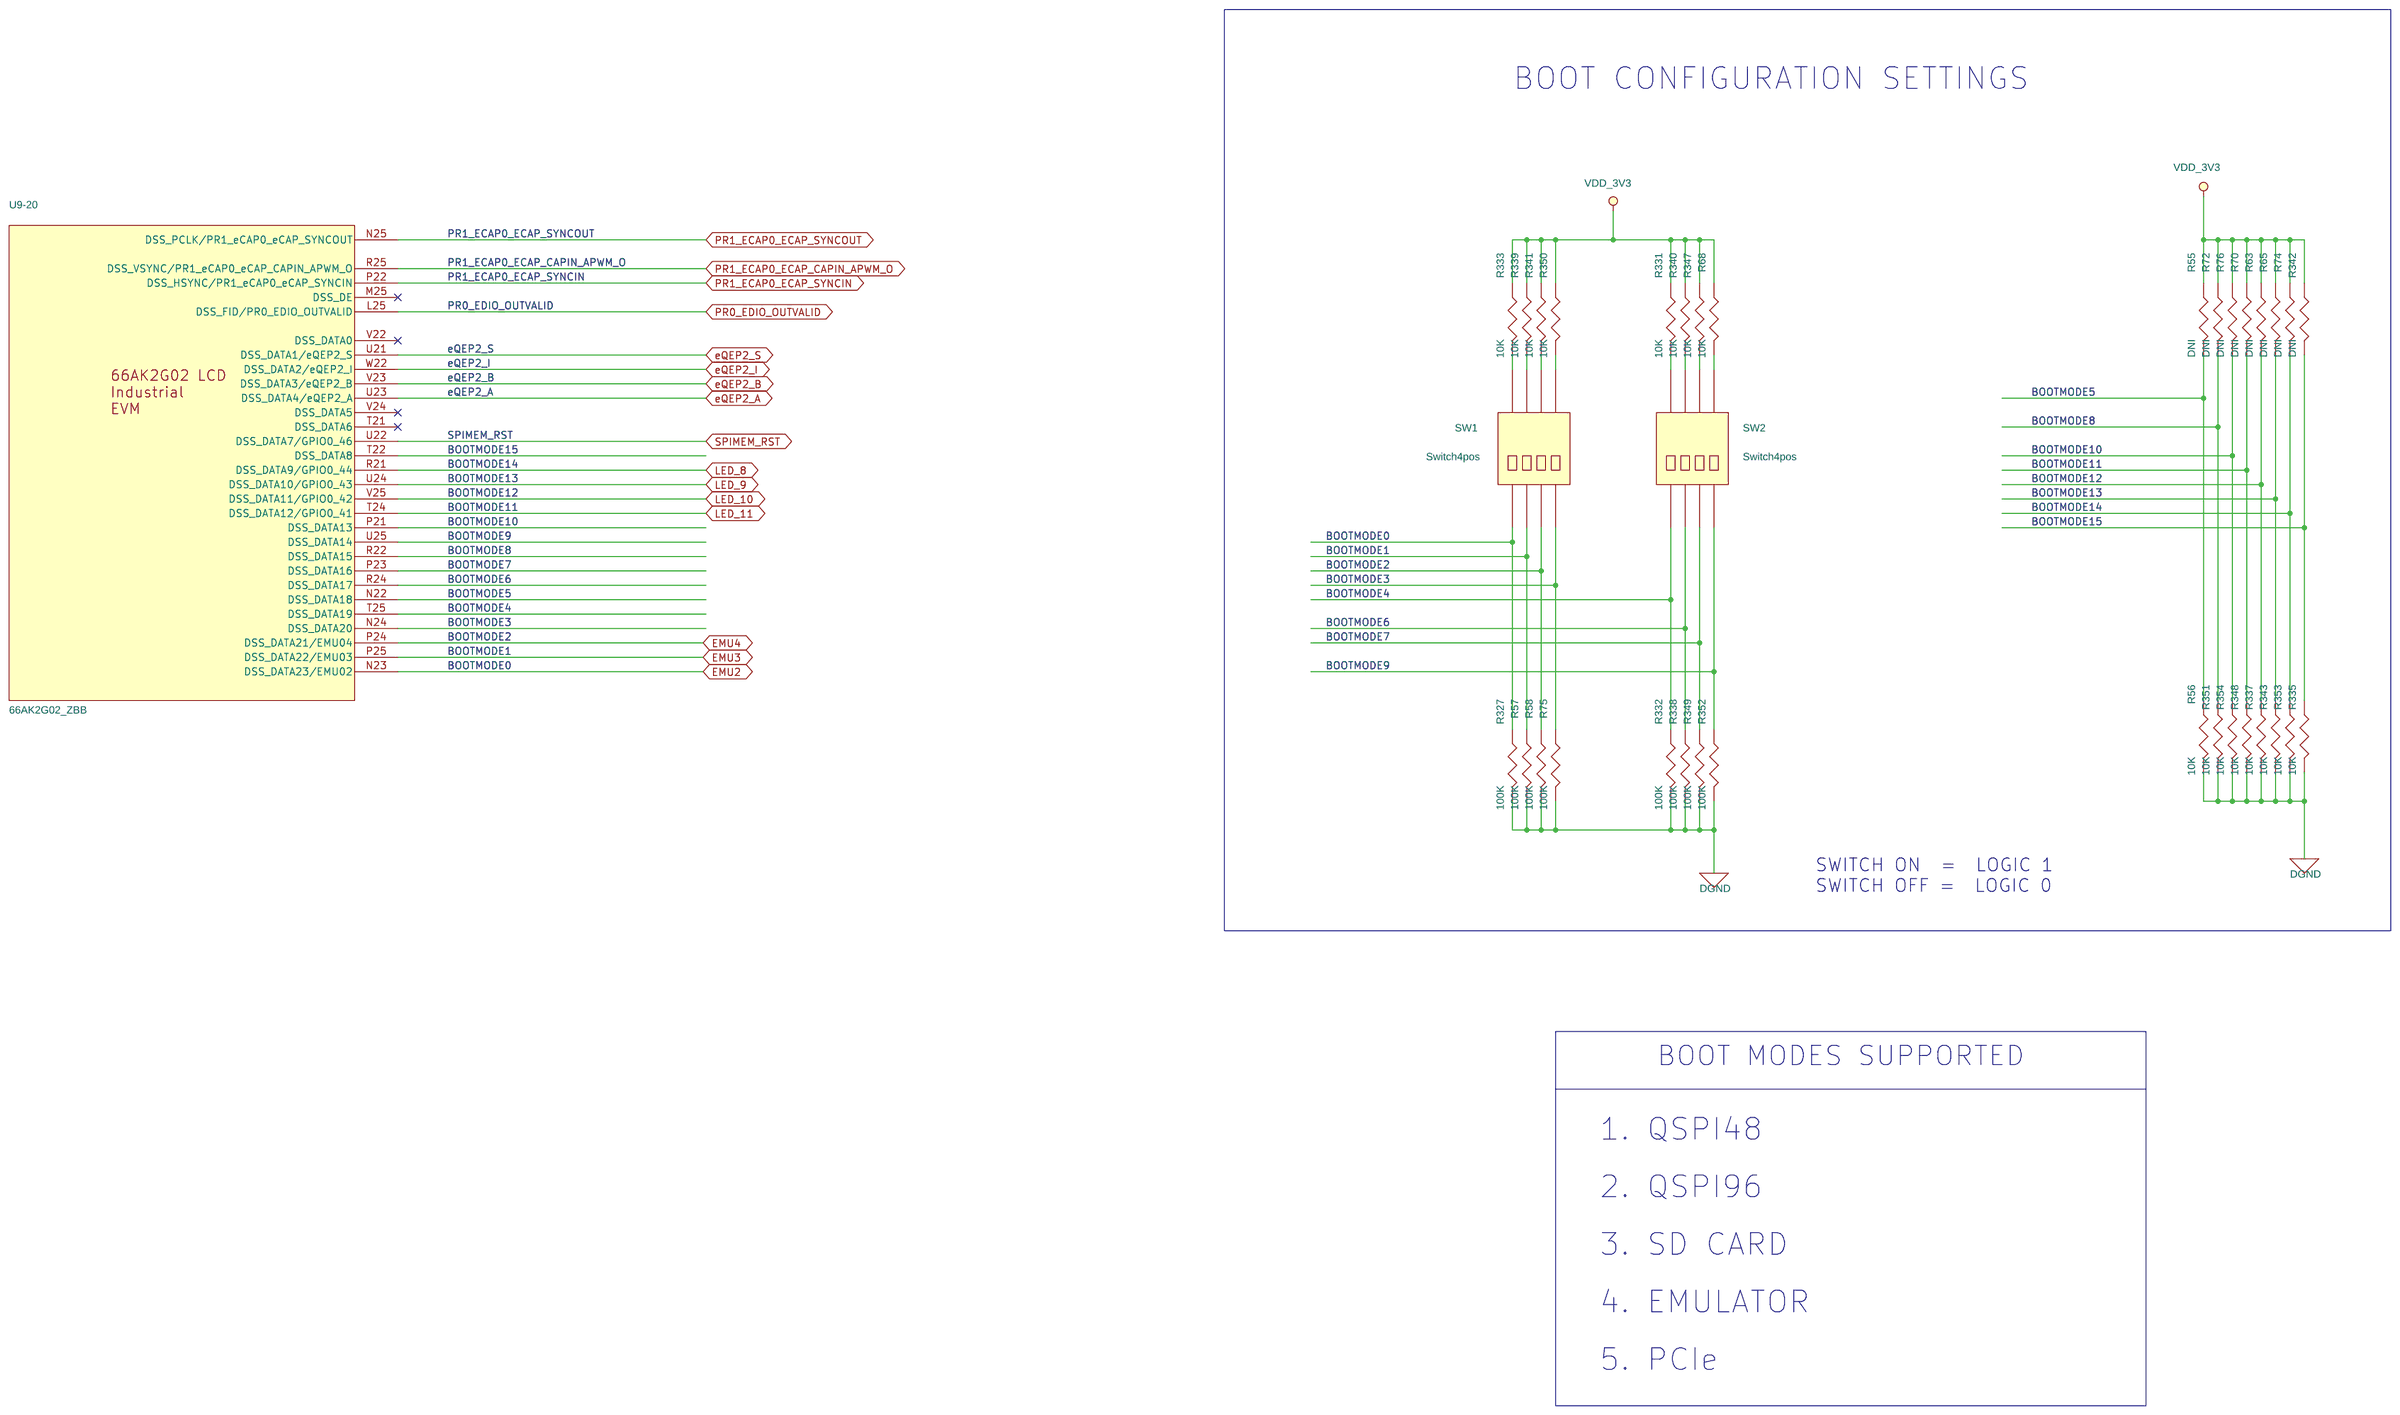
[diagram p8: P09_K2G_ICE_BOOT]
10 P10_DDR3L: size C; title: DDR3L
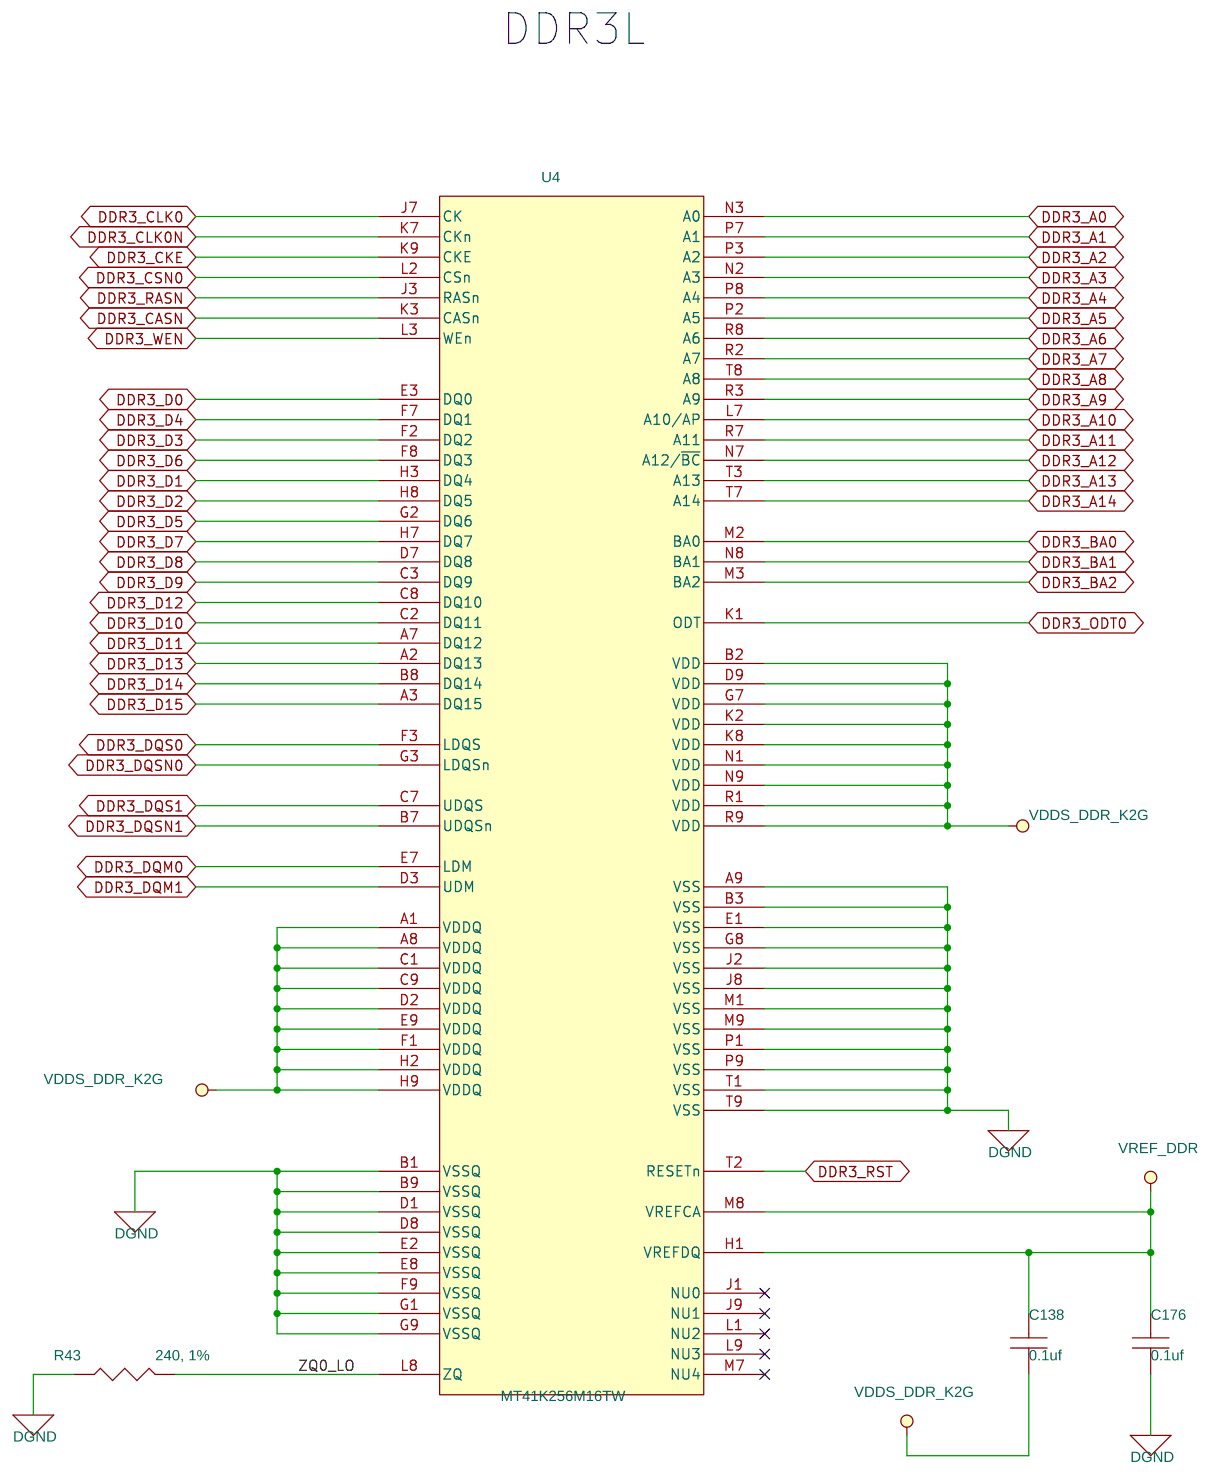
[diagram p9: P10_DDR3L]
11 P11_K2G_ICE_DDR3L DECAPS & TERM: size C; title: DDR3L DECAPS & TERMINATIONS
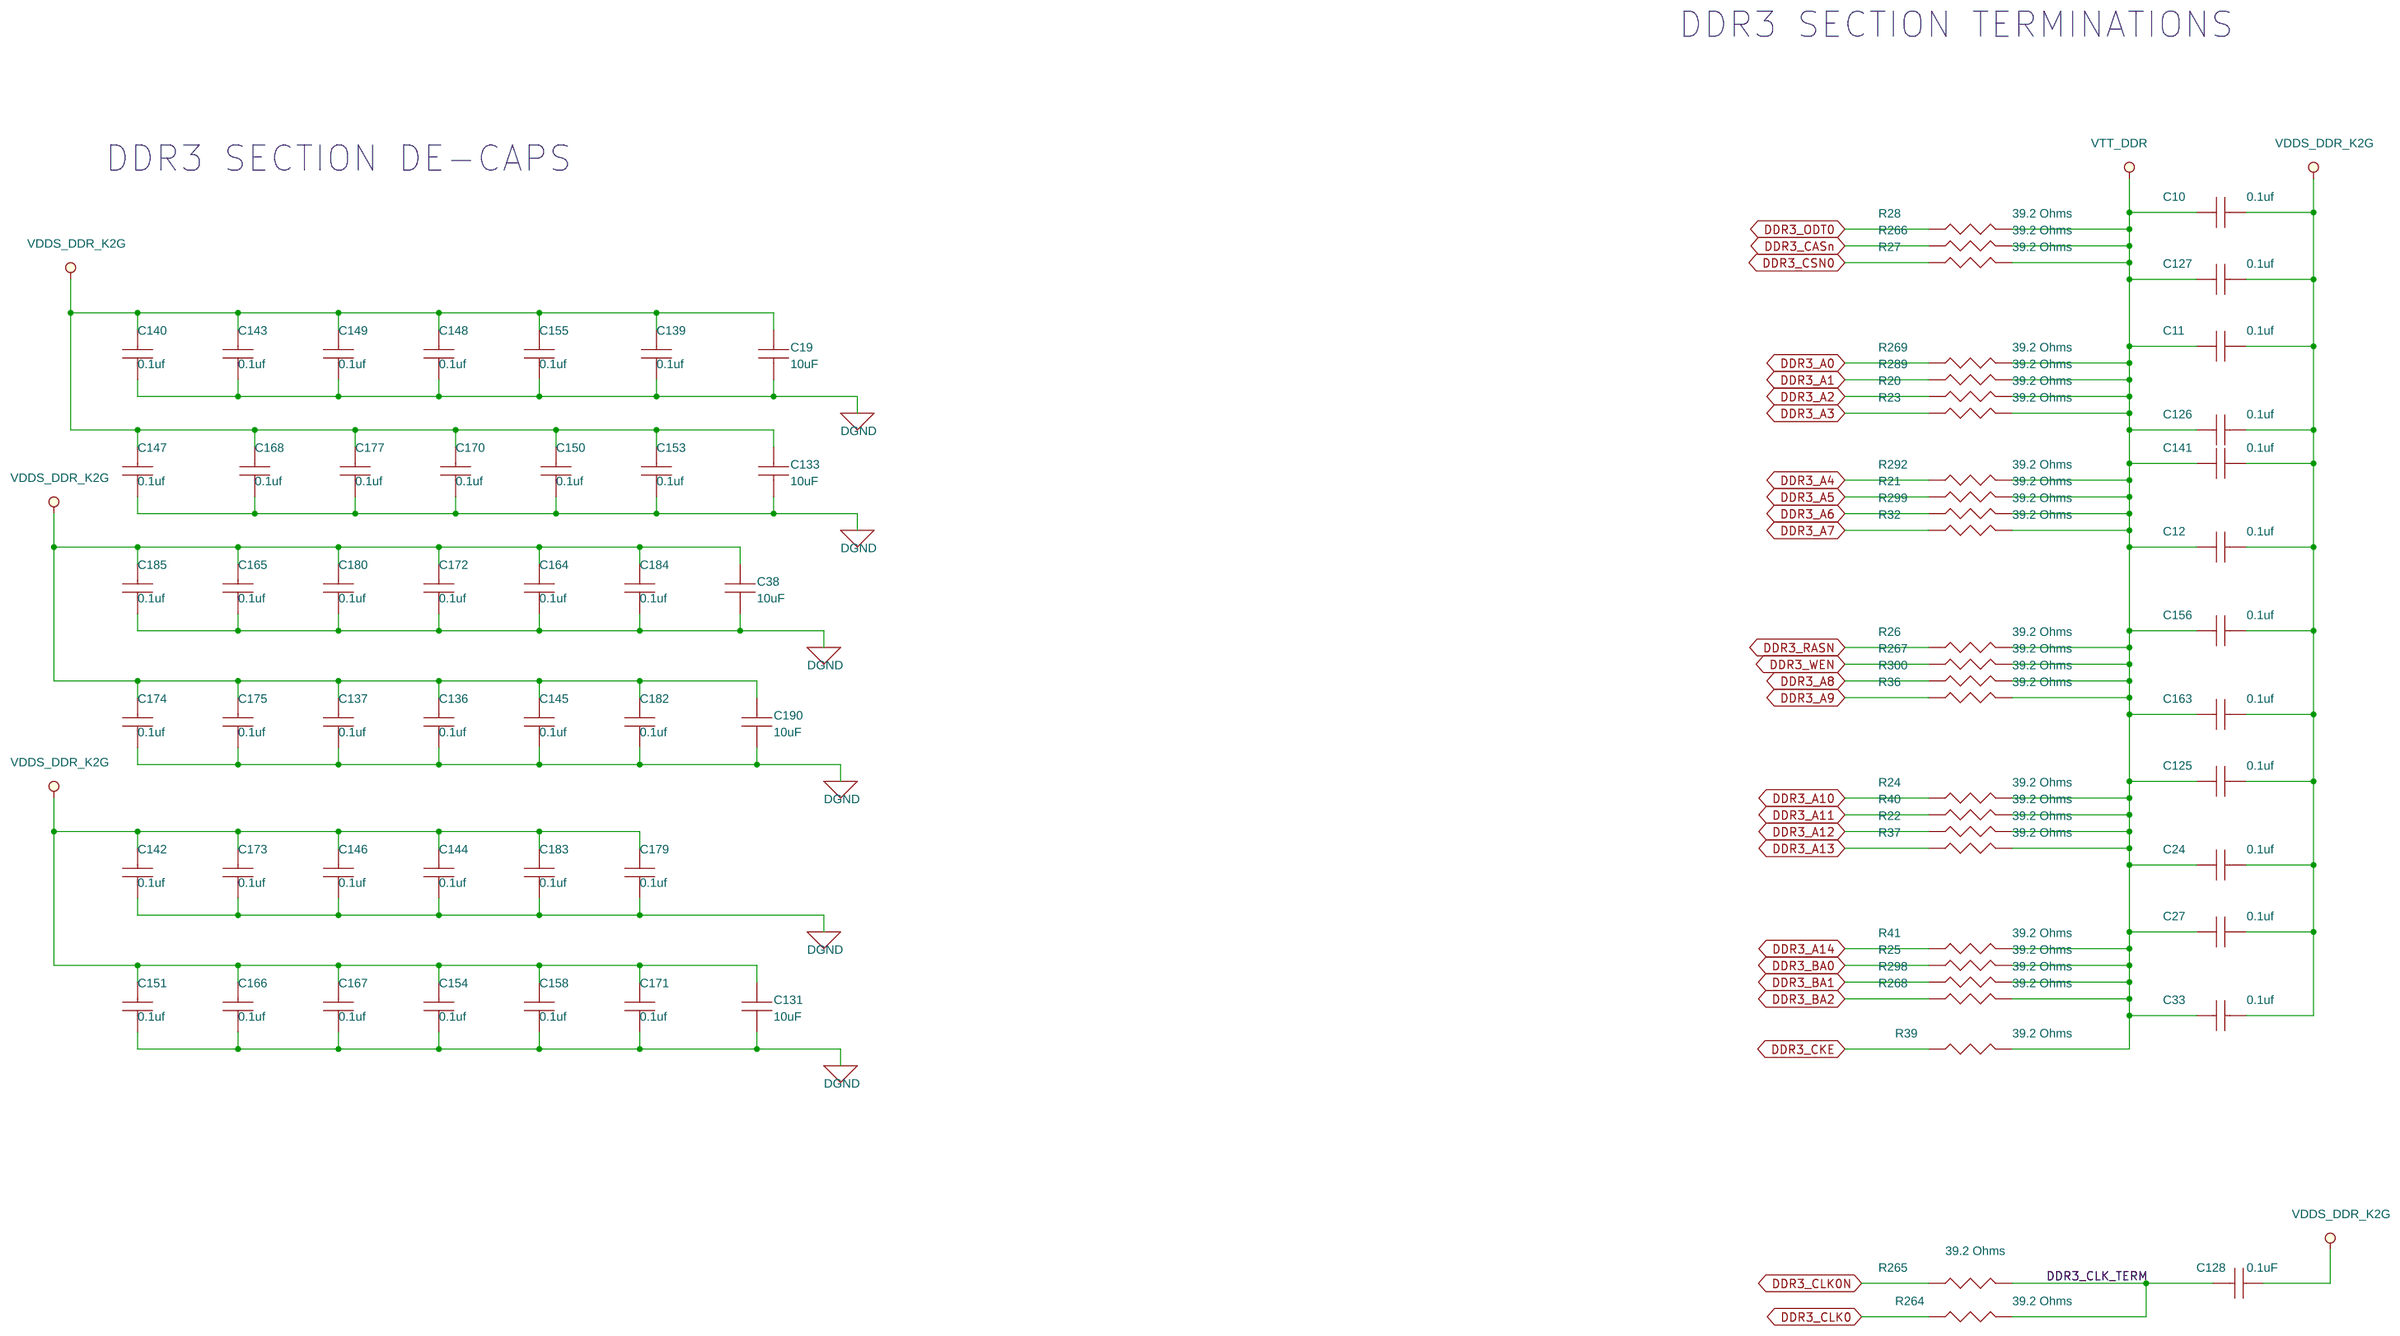
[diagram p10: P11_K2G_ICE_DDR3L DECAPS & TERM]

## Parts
sheet P04_K2G_PowerSupply1
C7  0.1uF  [SM-7351-CAP-0402]
C9  47uF, 10V  [SM-7351-CAP-1206]
C16  4.7uF  [SM-7351-CAP-0805]
C17  4.7uF  [SM-7351-CAP-0805]
C35  22uF  [SM-7351-CAP-0805]
C36  22uF  [SM-7351-CAP-0805]
C40  3300pF  [SM-7351-CAP-0402]
C106  47uF, 10V  [SM-7351-CAP-1206]
C112  22pF  [SM-7351-CAP-0402]
C113  47uF, 10V  [SM-7351-CAP-1206]
C114  2.2nF  [SM-7351-CAP-0402]
C115  0.01uF  [SM-7351-CAP-0402]
C120  47uF, 10V  [SM-7351-CAP-1206]
C121  0.1uF  [SM-7351-CAP-0402]
C124  0.22uF  [SM-7351-CAP-0603]
C130  0.01uF  [SM-7351-CAP-0805]
C132  22uF  [SM-7351-CAP-0805]
C135  0.01uF  [SM-7351-CAP-0805]
C157  22uF  [SM-7351-CAP-0805]
C160  10uF  [SM-7351-CAP-1206]
C181  10uF  [SM-7351-CAP-0805]
C191  47uF, 10V  [SM-7351-CAP-1206]
C202  10uF  [SM-7351-CAP-1206]
C209  22uF  [SM-7351-CAP-0805]
C380  0.01uF  [SM-7351-CAP-0402]
C381  0.1uF  [SM-7351-CAP-0402]
C394  0.1uF  [SM-7351-CAP-0402]
C425  0.1uF  [SM-7351-CAP-0402]
C426  0.01uF  [SM-7351-CAP-0402]
C427  DNI  [SM-7351-CAP-0402]
D1  Green LED  [sm_led_0805]
D11  CDBC540-G  [DO-214AB]
L1  1uH  [IND4X4-83M]
L2  1uH  [IND4X4-83M]
L6  4.7uH  [ind10x10-157m]
L8  1uH  [IND4X4-83M]
L9  1uH  [IND4X4-83M]
L11  1uH  [IND4X4-83M]
R10  330  [SM-7351-RES-0402]
R12  10.2K  [SM-7351-RES-0402]
R13  51.1Ohm  [SM-7351-RES-0402]
R14  1.96K  [sm-7351-res-0603]
R17  130K  [SM-7351-RES-0603]
R29  665K  [SM-7351-RES-0603]
R30  180K  [SM-7351-RES-0402]
R45  15K  [SM-7351-RES-0603]
R46  120K  [SM-7351-RES-0603]
R67  180K  [SM-7351-RES-0402]
R251  DNI  [SM-7351-RES-0402]
R252  4.7K  [SM-7351-RES-0402]
R253  37.4K  [SM-7351-RES-0402]
R281  127K  [sm-7351-res-0603]
R282  20K  [sm-7351-res-0603]
R293  180K  [SM-7351-RES-0402]
R294  78.7K  [sm-7351-res-0603]
R295  39.2K  [sm-7351-res-0603]
R324  39.2K  [sm-7351-res-0603]
R330  118K  [SM-7351-RES-0402]
R373  10K, 1%  [SM-7351-RES-0402]
R525  100K  [SM-7351-RES-0402]
R527  10K, 1%  [SM-7351-RES-0402]
SW3  B3SL  [SW_B3SL-1022P]
TP1  TP  [TH_TP_5002]
TP3  TP  [TH_TP_5002]
TP4  TP  [TH_TP_5002]
TP5  TP  [TH_TP_5002]
TP14  TP  [TH_TP_5002]
TP17  TP  [TH_TP_5002]
TP21  TP  [TH_TP_5002]
TP22  TP  [TH_TP_5002]
TP23  TP  [TH_TP_5002]
TP34  TP  [TH_TP_5002]
U5  TPS62180  [DSBGA2X3-24-25M]
U21  LP2996A  [SO4X5-8EP-67M]
U22  TPS54531  [SO4X5-8EP-67M]
U27  TLV62084  [WSON2X2-8-32M]
U30  TLV62080  [WSON2X2-8-32M]
U35  TLV62084  [WSON2X2-8-32M]
U149  TPS3808G09DBVR  [SOT23-6]
U150  SN74LVC1G08  [sm-so-sc70-5]
sheet P05_K2G_Power Supply2
C47  22uF  [SM-7351-CAP-0805]
C48  1uF  [SM-7351-CAP-0402]
C49  1uF  [SM-7351-CAP-0402]
C50  0.01uf  [SMD0201]
C51  0.01uf  [SMD0201]
C53  0.01uf  [SMD0201]
C58  1uF  [SM-7351-CAP-0402]
C195  22uF  [SM-7351-CAP-0805]
C196  4.7uF  [SM-7351-CAP-0603]
C197  1uF  [SM-7351-CAP-0402]
C198  1uF  [SM-7351-CAP-0402]
C200  2.2uF  [SM-7351-CAP-0402]
C201  0.22uF  [SMD0201]
C203  1uF  [SMD0201]
C204  0.22uF  [SMD0201]
C205  0.1uf  [SMD0201]
C206  0.1uf  [SMD0201]
C207  0.1uf  [SMD0201]
C208  1uF  [SM-7351-CAP-0402]
C210  0.1uF, 6.3V  [SMD0201]
C211  0.01uf  [SMD0201]
C213  0.22uF  [SMD0201]
C214  1uF  [SM-7351-CAP-0402]
C215  0.01uf  [SMD0201]
C216  0.1uf  [SMD0201]
C217  0.1uF, 6.3V  [SMD0201]
C218  0.1uF, 6.3V  [SMD0201]
C219  0.22uF  [SMD0201]
C220  0.01uf  [SMD0201]
C221  0.01uf  [SMD0201]
C222  0.1uF, 6.3V  [SMD0201]
C223  0.1uF, 6.3V  [SMD0201]
C224  0.1uF, 6.3V  [SMD0201]
C225  0.1uF, 6.3V  [SMD0201]
C226  0.22uF  [SMD0201]
C227  0.1uF, 6.3V  [SMD0201]
C228  0.1uF, 6.3V  [SMD0201]
C229  0.1uF, 6.3V  [SMD0201]
C230  0.1uF, 6.3V  [SMD0201]
C231  0.1uF, 6.3V  [SMD0201]
C232  0.1uF, 6.3V  [SMD0201]
C233  0.1uF, 6.3V  [SMD0201]
C234  0.1uF, 6.3V  [SMD0201]
C235  0.22uF  [SMD0201]
C236  0.1uF, 6.3V  [SMD0201]
C237  0.1uF, 6.3V  [SMD0201]
C238  0.01uf  [SMD0201]
C239  0.1uF, 6.3V  [SMD0201]
C240  0.1uF, 6.3V  [SMD0201]
C241  0.1uF, 6.3V  [SMD0201]
C243  0.1uF, 6.3V  [SMD0201]
C244  1uF  [SM-7351-CAP-0402]
C245  0.1uF, 6.3V  [SMD0201]
C247  0.01uf  [SMD0201]
C248  0.1uF, 6.3V  [SMD0201]
C249  0.1uF, 6.3V  [SMD0201]
C250  0.1uF, 6.3V  [SMD0201]
C251  0.1uF, 6.3V  [SMD0201]
C252  0.1uF, 6.3V  [SMD0201]
C253  0.1uF, 6.3V  [SMD0201]
C254  0.1uF, 6.3V  [SMD0201]
C255  0.1uF, 6.3V  [SMD0201]
C256  0.01uf  [SMD0201]
C257  0.01uf  [SMD0201]
C258  0.01uf  [SMD0201]
C259  0.1uF, 6.3V  [SMD0201]
C261  0.1uF, 6.3V  [SMD0201]
C262  1uF  [SM-7351-CAP-0402]
C263  0.1uF, 6.3V  [SMD0201]
C264  0.1uF, 6.3V  [SMD0201]
C265  0.1uF, 6.3V  [SMD0201]
C266  0.1uF, 6.3V  [SMD0201]
C267  1uF  [SMD0201]
C268  0.1uF, 6.3V  [SMD0201]
C269  0.1uF, 6.3V  [SMD0201]
C270  0.1uF, 6.3V  [SMD0201]
C271  0.1uF, 6.3V  [SMD0201]
C272  0.1uF, 6.3V  [SMD0201]
C273  1uF  [SMD0201]
C274  0.1uF, 6.3V  [SMD0201]
C275  0.1uF, 6.3V  [SMD0201]
C276  0.01uf  [SMD0201]
C277  0.01uf  [SMD0201]
C278  0.1uF, 6.3V  [SMD0201]
C279  0.1uF, 6.3V  [SMD0201]
C280  0.1uF, 6.3V  [SMD0201]
C281  0.1uF, 6.3V  [SMD0201]
C282  0.1uF, 6.3V  [SMD0201]
C283  0.01uf  [SMD0201]
C284  0.1uF, 6.3V  [SMD0201]
C285  0.01uf  [SMD0201]
C286  0.1uF, 6.3V  [SMD0201]
C287  0.01uf  [SMD0201]
C288  0.1uF, 6.3V  [SMD0201]
C289  0.1uF, 6.3V  [SMD0201]
C290  0.01uf  [SMD0201]
C291  0.1uF, 6.3V  [SMD0201]
C292  1uF  [SM-7351-CAP-0402]
C293  0.01uf  [SMD0201]
C294  0.01uf  [SMD0201]
C295  0.1uF, 6.3V  [SMD0201]
C296  0.01uf  [SMD0201]
C297  0.1uF, 6.3V  [SMD0201]
C298  0.01uf  [SMD0201]
C299  0.1uF, 6.3V  [SMD0201]
C300  0.1uF, 6.3V  [SMD0201]
C301  1uF  [SM-7351-CAP-0402]
C302  1uF  [SM-7351-CAP-0402]
C303  1uF  [SM-7351-CAP-0402]
C307  1uF  [SM-7351-CAP-0402]
C428  0.1uF, 6.3V  [SMD0201]
L3  NFM21PC474  [FILT-NFM21PC]
L4  NFM21PC474  [FILT-NFM21PC]
L5  NFM21PC474  [FILT-NFM21PC]
L10  NFM21PC474  [FILT-NFM21PC]
L12  NFM21PC474  [FILT-NFM21PC]
L14  NFM21PC474  [FILT-NFM21PC]
L15  NFM21PC474  [FILT-NFM21PC]
L16  NFM21PC474  [FILT-NFM21PC]
L17  NFM21PC474  [FILT-NFM21PC]
L18  NFM21PC474  [FILT-NFM21PC]
R367  0  [SM-7351-RES-1210]
R372  0  [SM-7351-RES-1210]
R378  0  [SM-7351-RES-1210]
sheet P06_K2G_SYSTEM_CLOCK_RESET_I2C
C45  24pF  [SM-7351-CAP-0402]
C46  24pF  [SM-7351-CAP-0402]
C194  0.01uF  [SM-7351-CAP-0402]
C408  10uF  [SM-7351-CAP-0805]
D20  Green LED  [sm_led_0805]
D22  Green LED  [sm_led_0805]
J3  HDR_2X1  [HDR_2X1_100_S_T]
Q11  BSS138  [TO_SOT23-123]
Q12  BSS138  [TO_SOT23-123]
Q15  MMUN2214LT1G  [SOT23-3]
R47  1K  [SM-7351-RES-0402]
R52  0  [SM-7351-RES-0402]
R53  DNI  [SM-7351-RES-0402]
R54  0  [SM-7351-RES-0402]
R69  4.7K  [SM-7351-RES-0402]
R71  4.7K  [SM-7351-RES-0402]
R73  4.7K  [SM-7351-RES-0402]
R260  330  [SM-7351-RES-0402]
R309  0  [SM-7351-RES-0402]
R322  10K  [SM-7351-RES-0402]
R323  10K  [SM-7351-RES-0402]
R325  10K  [SM-7351-RES-0402]
R326  0  [SM-7351-RES-0402]
R328  0  [SM-7351-RES-0402]
R344  10K  [SM-7351-RES-0402]
R346  10K  [SM-7351-RES-0402]
R356  DNI  [SM-7351-RES-0402]
R501  DNI  [SM-7351-RES-0402]
R504  10K  [SM-7351-RES-0402]
R505  330  [SM-7351-RES-0402]
R548  10K  [SM-7351-RES-0402]
R549  10K  [SM-7351-RES-0402]
R555  1K  [SM-7351-RES-0402]
R556  4.7K  [SM-7351-RES-0402]
R557  100K  [SM-7351-RES-0402]
R558  0  [SM-7351-RES-0402]
TP10  TP  [TH_TP_5002]
TP18  TP1mm  [tp_smd1mmcircle]
Y1  24MHz  [XTAL4_3P2X2P5_SMD]
sheet P07_K2G_ICE_DDR3L_INTERFACE
C212  0.1uf  [SMD0201]
R42  10K, 1%  [SM-7351-RES-0402]
R315  240, 1%  [SM-7351-RES-0402]
R336  240, 1%  [SM-7351-RES-0402]
R550  1K  [SM-7351-RES-0402]
R551  1K  [SM-7351-RES-0402]
R552  1K  [SM-7351-RES-0402]
R553  1K  [SM-7351-RES-0402]
TP12  TP1mm  [tp_smd1mmcircle]
sheet P08_K2G_ICE_EEPROM_ETHERNETLEDS
C310  4.7uF  [SM-7351-CAP-0603]
C353  0.1uF  [SM-7351-CAP-0402]
D14  Red_Green_Blue_LED  [LED-SM1210]
D15  Red_Green_Blue_LED  [LED-SM1210]
D17  Red_Green_Blue_LED  [LED-SM1210]
D18  Red_Green_Blue_LED  [LED-SM1210]
D19  Green LED  [sm_led_0805]
FB6  150OHM800mA  [sm-7351-ind-0805]
Q1  DMC564040R  [SMINI6-F3-B]  (sections A,B)
Q2  DMC564040R  [SMINI6-F3-B]  (sections A,B)
Q3  DMC564040R  [SMINI6-F3-B]  (sections A,B)
Q4  DMC564040R  [SMINI6-F3-B]  (sections A,B)
Q5  DMC564040R  [SMINI6-F3-B]  (sections A,B)
Q6  DMC564040R  [SMINI6-F3-B]  (sections A,B)
Q7  DMC564040R  [SMINI6-F3-B]  (sections A,B)
R111  330  [SM-7351-RES-0402]
R147  330  [SM-7351-RES-0402]
R148  330  [SM-7351-RES-0402]
R182  330  [SM-7351-RES-0402]
R191  330  [SM-7351-RES-0402]
R192  330  [SM-7351-RES-0402]
R208  330  [SM-7351-RES-0402]
R209  330  [SM-7351-RES-0402]
R235  330  [SM-7351-RES-0402]
R237  330  [SM-7351-RES-0402]
R388  DNI  [SM-7351-RES-0402]
R401  DNI  [SM-7351-RES-0402]
R412  1K  [SM-7351-RES-0402]
R422  DNI  [SM-7351-RES-0402]
R426  DNI  [SM-7351-RES-0402]
R429  1K  [SM-7351-RES-0402]
R431  1K  [SM-7351-RES-0402]
R432  330  [SM-7351-RES-0402]
R435  1K  [SM-7351-RES-0402]
R441  1K  [SM-7351-RES-0402]
R448  1K  [SM-7351-RES-0402]
R453  330  [SM-7351-RES-0402]
R454  1K  [SM-7351-RES-0402]
R455  1K  [SM-7351-RES-0402]
R457  330  [SM-7351-RES-0402]
R458  0  [SM-7351-RES-0402]
R460  1K  [SM-7351-RES-0402]
R469  DNI  [SM-7351-RES-0402]
TP26  TP1mm  [tp_smd1mmcircle]
TP33  TP1mm  [tp_smd1mmcircle]
U52  CAT24C256W  [SOIC8_MC]
sheet P09_K2G_ICE_BOOT
R55  DNI  [SM-7351-RES-0402]
R56  10K  [SM-7351-RES-0402]
R57  100K  [SM-7351-RES-0402]
R58  100K  [SM-7351-RES-0402]
R63  DNI  [SM-7351-RES-0402]
R65  DNI  [SM-7351-RES-0402]
R68  10K  [SM-7351-RES-0402]
R70  DNI  [SM-7351-RES-0402]
R72  DNI  [SM-7351-RES-0402]
R74  DNI  [SM-7351-RES-0402]
R75  100K  [SM-7351-RES-0402]
R76  DNI  [SM-7351-RES-0402]
R327  100K  [SM-7351-RES-0402]
R331  10K  [SM-7351-RES-0402]
R332  100K  [SM-7351-RES-0402]
R333  10K  [SM-7351-RES-0402]
R335  10K  [SM-7351-RES-0402]
R337  10K  [SM-7351-RES-0402]
R338  100K  [SM-7351-RES-0402]
R339  10K  [SM-7351-RES-0402]
R340  10K  [SM-7351-RES-0402]
R341  10K  [SM-7351-RES-0402]
R342  DNI  [SM-7351-RES-0402]
R343  10K  [SM-7351-RES-0402]
R347  10K  [SM-7351-RES-0402]
R348  10K  [SM-7351-RES-0402]
R349  100K  [SM-7351-RES-0402]
R350  10K  [SM-7351-RES-0402]
R351  10K  [SM-7351-RES-0402]
R352  100K  [SM-7351-RES-0402]
R353  10K  [SM-7351-RES-0402]
R354  10K  [SM-7351-RES-0402]
SW1  Switch4pos  [219-4MST]
SW2  Switch4pos  [219-4MST]
sheet P10_DDR3L
C138  0.1uf  [SMD0201]
C176  0.1uf  [SMD0201]
R43  240, 1%  [SM-7351-RES-0402]
U4  MT41K256M16TW  [bga9x14-96]
sheet P11_K2G_ICE_DDR3L DECAPS & TERM
C10  0.1uf  [SMD0201]
C11  0.1uf  [SMD0201]
C12  0.1uf  [SMD0201]
C19  10uF  [SM-7351-CAP-0603]
C24  0.1uf  [SMD0201]
C27  0.1uf  [SMD0201]
C33  0.1uf  [SMD0201]
C38  10uF  [SM-7351-CAP-0603]
C125  0.1uf  [SMD0201]
C126  0.1uf  [SMD0201]
C127  0.1uf  [SMD0201]
C128  0.1uF  [SM-7351-CAP-0402]
C131  10uF  [SM-7351-CAP-0603]
C133  10uF  [SM-7351-CAP-0603]
C136  0.1uf  [SMD0201]
C137  0.1uf  [SMD0201]
C139  0.1uf  [SMD0201]
C140  0.1uf  [SMD0201]
C141  0.1uf  [SMD0201]
C142  0.1uf  [SMD0201]
C143  0.1uf  [SMD0201]
C144  0.1uf  [SMD0201]
C145  0.1uf  [SMD0201]
C146  0.1uf  [SMD0201]
C147  0.1uf  [SMD0201]
C148  0.1uf  [SMD0201]
C149  0.1uf  [SMD0201]
C150  0.1uf  [SMD0201]
C151  0.1uf  [SMD0201]
C153  0.1uf  [SMD0201]
C154  0.1uf  [SMD0201]
C155  0.1uf  [SMD0201]
C156  0.1uf  [SMD0201]
C158  0.1uf  [SMD0201]
C163  0.1uf  [SMD0201]
C164  0.1uf  [SMD0201]
C165  0.1uf  [SMD0201]
C166  0.1uf  [SMD0201]
C167  0.1uf  [SMD0201]
C168  0.1uf  [SMD0201]
C170  0.1uf  [SMD0201]
C171  0.1uf  [SMD0201]
C172  0.1uf  [SMD0201]
C173  0.1uf  [SMD0201]
C174  0.1uf  [SMD0201]
C175  0.1uf  [SMD0201]
C177  0.1uf  [SMD0201]
C179  0.1uf  [SMD0201]
C180  0.1uf  [SMD0201]
C182  0.1uf  [SMD0201]
C183  0.1uf  [SMD0201]
C184  0.1uf  [SMD0201]
C185  0.1uf  [SMD0201]
C190  10uF  [SM-7351-CAP-0603]
R20  39.2 Ohms  [SM-7351-RES-0402]
R21  39.2 Ohms  [SM-7351-RES-0402]
R22  39.2 Ohms  [SM-7351-RES-0402]
R23  39.2 Ohms  [SM-7351-RES-0402]
R24  39.2 Ohms  [SM-7351-RES-0402]
R25  39.2 Ohms  [SM-7351-RES-0402]
R26  39.2 Ohms  [SM-7351-RES-0402]
R27  39.2 Ohms  [SM-7351-RES-0402]
R28  39.2 Ohms  [SM-7351-RES-0402]
R32  39.2 Ohms  [SM-7351-RES-0402]
R36  39.2 Ohms  [SM-7351-RES-0402]
R37  39.2 Ohms  [SM-7351-RES-0402]
R39  39.2 Ohms  [SM-7351-RES-0402]
R40  39.2 Ohms  [SM-7351-RES-0402]
R41  39.2 Ohms  [SM-7351-RES-0402]
R264  39.2 Ohms  [SM-7351-RES-0402]
R265  39.2 Ohms  [SM-7351-RES-0402]
R266  39.2 Ohms  [SM-7351-RES-0402]
R267  39.2 Ohms  [SM-7351-RES-0402]
R268  39.2 Ohms  [SM-7351-RES-0402]
R269  39.2 Ohms  [SM-7351-RES-0402]
R289  39.2 Ohms  [SM-7351-RES-0402]
R292  39.2 Ohms  [SM-7351-RES-0402]
R298  39.2 Ohms  [SM-7351-RES-0402]
R299  39.2 Ohms  [SM-7351-RES-0402]
R300  39.2 Ohms  [SM-7351-RES-0402]
sheet P17_K2G_ICE_PRU1MII1_Ethernet 3
U9  66AK2G02_ZBB  [BGA21X21-625-67M]  (sections -1,-10,-11,-12,-13,-14,-15,-16,-17,-18,-19,-2,-20,-21,-22,-23,-24,-25,-26,-27,-28,-3,-4,-5,-6,-7,-8,-9)

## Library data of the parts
C7 C128 C353 C381 C394 C425 = 1C_0.1uFCapacitor16V10%0402: MfrNum: C0402C104K4RACTU
C9 C106 C113 C120 C191 = 1C_47uFCapacitor10V20%SMD1206
C16 C17 = 1C_4.7uFCapacitor50V20%0805: MfrNum: C2012X5R1H475M125AB
C35 C36 C132 C157 C209 = 1C_22uFCapacitor16V10%0805
C40 = 1C_3300pFCapacitor100V10%0402
C112 = 1C_22pFCapacitor50V10%SMD0402
C114 = 1C_2.2nF100V10%SMD0402
C115 C194 C380 C426 = 1C_0.01uFCapacitor16V10%0402
C121 = 1C_0.1uFCapacitor50V10%0402: MfrNum: C1005X7R1H104K050BB
C124 = 1C_0.22uFCapacitor50V10%0603
C130 C135 = 1C_CAP_0.01uF_X7R_50V_20%_0805
C160 C202 = 1C_10uFCapacitor50V10%1206: MfrNum: C3216X5R1H106K160AB
C181 C408 = 1C_10uFCapacitor16V10%0805
C427 = 1C_0.1uFCapacitor16V10%0402
D1 = LED_Green: MfrNum: 5988170107F
D11 = Diode_5A40V
L1 L2 = 1L_1uHInductor20%4.5Asmd: MfrNum: XFL4020-102MEB
L6 = 1L_4.7uHInductor7Asmd
L8 L9 L11 = 1L_1uHInductor20%2.5Asmd
R10 R111 R147 R148 R182 R191 R192 R208 R209 R235 R237 R260 R432 R453 R457 R505 = 1R_330ohm1_16W5%smd0402
R12 = 1R_10.2KOhmResistor1_16W0402
R13 = 1R_51.1OhmResistor1_16W0402
R14 = 1R_1.96KOhmResistor1_10W1%0603
R17 = 1R_130KOhmResistor1_10W0603
R29 = 1R_665KOhmResistor1_10W0603
R30 R67 R293 = 1R_180KOhmResistor1_16W0402
R45 = 1R_15KOhmResistor1_16W0603
R46 = 1R_120KOhmResistor1_16W0603
R69 R71 R73 R251 R252 R356 R556 = 1R_4.7KOhmResistor1_16W0402
R253 = 1R_37.4Kohm1_16W1%smd0402
R281 = 1R_127KOhmResistor1_10W1%0603
R282 = 1R_20KOhmResistor1_10W1%0603
R294 = 1R_78.7KOhmResistor1_10W1%0603
R295 R324 = 1R_39.2KOhmResistor1_10W1%0603
R330 = 1R_118KOhmResistor1_16W0402
R42 R373 R469 R527 = 1R_10KOhmResistor1_10W1%0402
R55 R57 R58 R63 R65 R70 R72 R74-R76 R327 R332 R338 R342 R349 R352 R525 R557 = 1R_100KOhmResistor1_16W0402
SW3 = 2W_Switch_Pushbuttonsmd
TP1 TP21 TP22 TP34 = TestPointThroughHole
TP3-TP5 TP10 TP14 TP17 TP23 = 2H_TestPointThroughHole
U5 = 1A_TPS62180
U21 = LP2996A
U22 = 1A_TPS54531
U27 U35 = TLV62084: MfrNum: TLV62084DSGR
U30 = TLV62080: MfrNum: TLV62080DSGT
U149 = TPS3808G09DBVR_SOT23-6: IC µP SUPERVISOR CIRCUITS SOT23-6; Crtd /date: VASANTHA/270516; Custom_Duty: 15%; Customs_HS_Code: 85423100; DescriptiveText: IC µP SUPERVISOR CIRCUITS SOT23-6; Distributor_name: DIGIKEY; Distributor_part_number: 296-17189-1-ND; Height: 1.45MM; Mfr: TEXAS INSTRUMENTS; Mfr_name: TEXAS INSTRUMENTS; Mistral Part No: 142010050005-P; Mistral part number: NSPN00394; Part_type: ICS\POWER; Project: CENTAURUS; RoHS: RoHS; Temperature: -40°C to 125°C; Datasheet: Y:\MIS_DATABASE\DATASHEETS\ICS\POWER\TPS3808G50.PDF
U150 = 1A_SN74LVC1G08DCKT_SC70: MfrNum: SN74LVC1G08DCKR
C47 C195 = 1C_CAP_22uF_X5R_16V_20%_0805
C48 C49 C58 C197 C198 C208 C214 C244 C262 C292 C301-C303 C307 = 1C_1uFCapacitor10V10%0402
C50 C51 C53 C211 C215 C220 C221 C238 C247 C256-C258 C276 C277 C283 C285 C287 C290 C293 C294 C296 C298 = 1C_CAP_0.01uF_X7R_10V_20%_0201
C196 = 1C_CAP_4.7uF_X5R_10V_20%_0603
C200 = 1C_CAP_2.2uF_X5R_10V_10%_0402
C201 C204 C213 C219 C226 C235 = 1C_CAP_0.22uf_X5R_16V_20%_0201
C203 C267 C273 = 1C_CAP_1.0UF_X5R_10V_0201
C10-C12 C24 C27 C33 C125-C127 C136-C151 C153-C156 C158 C163-C168 C170-C177 C179 C180 C182-C185 C205-C207 C212 C216 = 1C_CAP_0.1uF_X5R_16V_20%_0201
C210 C217 C218 C222-C225 C227-C234 C236 C237 C239-C241 C243 C245 C248-C255 C259 C261 C263-C266 C268-C272 C274 C275 C278-C282 C284 C286 C288 C289 C291 C295 C297 C299 C300 C428 = 1C_CAP0.1uFCapacitor6.3V10%0201
L3-L5 L10 L12 L14-L18 = 1L_NFM21PC474_EMIFilter
R367 R372 R378 = 1R_ZeroOhmResistor1_2W1210
C45 C46 = 1C_24pFCapacitor50V5%SMD0402
D19 D20 D22 = 1F_LED_Green: MfrNum: 5988170107F
J3 = HEADER_2X1: Crtd /date: VASANTHA/170516; DescriptiveText: CON HDR 2X1 2.54MM PITCH ST TH; Mfr: MOLEX; MfrNum: 0022032021; Mistral part number: NSPN00390; Part_type: CONNECTOR\HEADER
Q11 Q12 = MOSFET_BSS138: Crtd /date: VASANTHA/170516; DescriptiveText: IC MOSFET N-CHANNEL 50V 200mA SOT23-3; Mfr: DIODES INC; MfrNum: BSS138-7-F; Mistral part number: NSPN00386; Part_type: ICS\POWER\MOSFET
Q15 = NPN_123_SOT23-3_BRT: TRANSISTOR NPN 50V100mA SOT23-3; Crtd /date: VASANTHA/130516; DescriptiveText: TRANSISTOR NPN 50V100mA SOT23-3; Manufacturer: ON SEMICONDUCTOR; Mfr: ON SEMICONDUCTOR; Mistral part number: NSPN00354; Part_type: TRANSISTOR\BIPOLAR
R47 R388 R401 R412 R422 R426 R429 R431 R435 R441 R448 R454 R455 R460 R550-R553 R555 = 1R_1KOhmResistor1_16W0402
R52 R54 R309 R326 R328 R458 R558 = 1R_ZeroOhmResistor1_16W0402
R53 = 1R_1MOhmResistor1_16W0402
R56 R68 R322 R323 R325 R331 R333 R335 R337 R339-R341 R343 R344 R346-R348 R350 R351 R353 R354 R501 R504 R548 R549 = 1R_10KOhmResistor1_16W0402
TP12 TP18 = 2H_Testpoint_SMD1mmCircle
Y1 = Crystal24MHz18PFsmd_0: MfrNum: CS325S24000000ABJT
R43 R315 R336 = 1R_240OhmResistor1_10W1%0402
C310 = 4.7uFCapacitor16V10%0603
D14 D15 D17 D18 = 1F_LED_Tricolor_RedGreenYellow: DescriptiveText: LED RedGreenBlue Tricolor 20mA 1.9/2.1V 1210 smd; MfrNum: SM1210RGB
FB6 = FerBead_180ohm200mA
Q1-Q7 = NPN_DMC564040R
TP26 TP33 = Testpoint_SMD1mmCircle
U52 = 1A_CAT24C256W
SW1 SW2 = 2W_SwitchDIP4pos_smd
U4 = 1A_MT41K256M16HA: MfrNum: MT41K256M16TW-107 IT
C19 C38 C131 C133 C190 = 1C_10uFCapacitor6.3V20%0603
R20-R28 R32 R36 R37 R39-R41 R264-R269 R289 R292 R298-R300 = 1R_39.2OhmResistor1_16W0402
U9 = 66AK2G02-ZBB_BGA625: Crtd /date: VASANTHA/090616; DescriptiveText: IC ARM CORTEX AND DSP 32 BIT MICROPROCESSOR BGA625; Mfr: TEXAS INSTRUMENTS; Mistral part number: NSPN00330; Part_type: ICS\DIGITAL\MICROPROCESSOR

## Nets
AVDDA_DSSPLL: C244.1 C257.1 C258.1 L14.3(OUT) U9.N20(AVDDA_DSSPLL)
AVDDA_MAINPLL: C49.1 C50.1 C256.1 L3.3(OUT) U9.M19(AVDDA_MAINPLL)
DGND: C9.2 C16.2 C17.2 C19.2 C35.2 C36.2 C38.2 C40.2 C47.2 C48.2 C49.2 C50.2 C51.2 C53.2 C58.2 C106.2 C112.2 C113.2 C115.2 C120.2 C124.2 C130.2 C131.2 C132.2 C133.2 C135.2 C136.2 C137.2 C139.2 C140.2 C142.2 C143.2 C144.2 C145.2 C146.2 C147.2 C148.2 C149.2 C150.2 C151.2 C153.2 C154.2 C155.2 C157.2 C158.2 C160.2 C164.2 C165.2 C166.2 C167.2 C168.2 C170.2 C171.2 C172.2 C173.2 C174.2 C175.2 C176.2 C177.2 C179.2 C180.2 C181.2 C182.2 C183.2 C184.2 C185.2 C190.2 C191.2 C194.2 C195.2 C196.2 C197.2 C198.2 C200.1 C201.2 C202.2 C203.2 C204.2 C205.2 C206.2 C207.2 C208.2 C209.2 C210.2 C211.2 C212.2 C213.2 C214.2 C215.2 C216.2 C217.2 C218.2 C219.2 C220.2 C221.2 C222.2 C223.2 C224.2 C225.2 C226.1 C227.2 C228.2 C229.2 C230.2 C231.2 C232.2 C233.2 C234.2 C235.1 C236.2 C237.2 C238.2 C239.2 C240.2 C241.2 C243.2 C244.2 C245.2 C247.2 C248.2 C249.2 C250.2 C251.2 C252.2 C253.2 C254.2 C255.2 C256.2 C257.2 C258.2 C259.2 C261.2 C262.2 C263.2 C264.2 C265.2 C266.2 C267.2 C268.2 C269.2 C270.2 C271.2 C272.2 C273.2 C274.2 C275.2 C276.2 C277.2 C278.2 C279.2 C280.2 C281.2 C282.2 C283.2 C284.2 C285.2 C286.2 C287.2 C288.2 C289.2 C290.2 C291.2 C292.2 C293.2 C294.2 C295.2 C296.2 C297.2 C298.2 C299.2 C300.2 C301.2 C302.2 C303.2 C307.2 C310.2 C353.2 C380.2 C381.2 C394.1 C408.2 C425.1 C426.2 C427.1 C428.1 D1.1(Cathode) D11.2(ANODE) L3.2(GND) L4.2(GND) L5.2(GND) L10.2(GND) L12.2(GND) L14.2(GND) L15.2(GND) L16.2(GND) L17.2(GND) L18.2(GND) Q1.1(4) Q1.4 Q2.1(4) Q2.4 Q3.1(4) Q3.4 Q4.1(4) Q4.4 Q5.1(4) Q5.4 Q6.1(4) Q6.4 Q7.1(4) Q11.2(S) Q12.2(S) Q15.2(EMITTER) R14.1(P1) R17.1(P1) R42.1 R43.1 R46.1(P1) R47.1(P1) R52.2(P2) R56.1(P1) R57.1(P1) R58.1(P1) R75.1(P1) R251.1(P1) R253.1(P1) R282.1(P1) R295.1(P1) R315.1 R324.1(P1) R327.1(P1) R332.1(P1) R335.1(P1) R336.1 R337.1(P1) R338.1(P1) R343.1(P1) R348.1(P1) R349.1(P1) R351.1(P1) R352.1(P1) R353.1(P1) R354.1(P1) R356.1(P1) R388.1(P1) R401.1(P1) R412.1(P1) R422.1(P1) R426.1(P1) R429.1(P1) R431.1(P1) R435.1(P1) R441.1(P1) R448.1(P1) R454.1(P1) R455.1(P1) R460.1(P1) R551.2(P2) R553.2(P2) R555.1(P1) SW3.1 SW3.2 TP1.1 TP21.1 TP22.1 TP34.1 U4.A9(VSS) U4.B1(VSSQ) U4.B3(VSS) U4.B9(VSSQ) U4.D1(VSSQ) U4.D8(VSSQ) U4.E1(VSS) U4.E2(VSSQ) U4.E8(VSSQ) U4.F9(VSSQ) U4.G1(VSSQ) U4.G8(VSS) U4.G9(VSSQ) U4.J2(VSS) U4.J8(VSS) U4.M1(VSS) U4.M9(VSS) U4.P1(VSS) U4.P9(VSS) U4.T1(VSS) U4.T9(VSS) U5.A3(PGND1) U5.B3(PGND2) U5.C3(PGND3) U5.C4(AGND) U5.D3(PGND4) U5.E3(PGND5) U5.F3(PGND6) U9.A1(VSS) U9.A25(VSS) U9.AD8(VSS) U9.AD14(VSS) U9.AE1(VSS) U9.AE5(VSS) U9.AE11(VSS) U9.AE18(VSS) U9.AE25(VSS) U9.B17(VSS_OSC_AUDIO) U9.C1(VSS) U9.E2(VSS) U9.E22(VSS) U9.F1(VSS) U9.F3(VSS) U9.F6(VSS) U9.F8(VSS) U9.F20(VSS) U9.G7(VSS) U9.G9(VSS) U9.G11(VSS) U9.G13(VSS) U9.G15(VSS) U9.G17(VSS) U9.G19(VSS) U9.G21(VSS) U9.H6(VSS) U9.H8(VSS) U9.H10(VSS) U9.H12(VSS) U9.H14(VSS) U9.H16(VSS) U9.H18(VSS) U9.H20(VSS) U9.J1(VSS) U9.J7(VSS) U9.J9(VSS) U9.J11(VSS) U9.J13(VSS) U9.J15(VSS) U9.J17(VSS) U9.J19(VSS) U9.K6(VSS) U9.K8(VSS) U9.K10(VSS) U9.K12(VSS) U9.K14(VSS) U9.K16(VSS) U9.K18(VSS) U9.K20(VSS) U9.L7(VSS) U9.L9(VSS) U9.L11(VSS) U9.L13(VSS) U9.L15(VSS) U9.L17(VSS) U9.L19(VSS) U9.M6(VSS) U9.M8(VSS) U9.M10(VSS) U9.M12(VSS) U9.M14(VSS) U9.M16(VSS) U9.M18(VSS) U9.M20(VSS) U9.N7(VSS) U9.N9(VSS) U9.N11(VSS) U9.N13(VSS) U9.N15(VSS) U9.N17(VSS) U9.N19(VSS) U9.N21(VSS) U9.P6(VSS) U9.P8(VSS) U9.P10(VSS) U9.P12(VSS) U9.P14(VSS) U9.P16(VSS) U9.P18(VSS) U9.P20(VSS) U9.R7(VSS) U9.R9(VSS) U9.R11(VSS) U9.R13(VSS) U9.R15(VSS) U9.R17(VSS) U9.R19(VSS) U9.R23(VSS) U9.T6(VSS) U9.T8(VSS) U9.T10(VSS) U9.T12(VSS) U9.T14(VSS) U9.T16(VSS) U9.T18(VSS) U9.T20(VSS) U9.U7(VSS) U9.U9(VSS) U9.U11(VSS) U9.U13(VSS) U9.U15(VSS) U9.U17(VSS) U9.U19(VSS) U9.V8(VSS) U9.V10(VSS) U9.V12(VSS) U9.V14(VSS) U9.V16(VSS) U9.V18(VSS) U9.V20(VSS) U9.W7(VSS) U9.W9(VSS) U9.W11(VSS) U9.W13(VSS) U9.W15(VSS) U9.W17(VSS) U9.Y10(VSS) U9.Y23(VSS) U21.1(GND) U21.TPAD U22.7(GND) U22.TPAD(PPAD) U27.2(GND1) U27.3(GND2) U27.TPAD U30.2(GND1) U30.3(GND2) U30.TPAD U35.2(GND1) U35.3(GND2) U35.TPAD U52.1(A0) U52.2(A1) U52.3(A2) U52.4(VSS) U149.2(GND) U150.3(GND) ; also on sheet 12 13 14 15 16 17 18 19 20 21 22 23 24 25 26 27 28 29
DVDD18_PCIE: R367.1(P1) U9.G6(DVDD18)
DVDD18_USB: R372.1(P1) U9.F19(DVDD18)
DVDD_3V3: R378.1(P1) U9.G18(DVDD33_USB) U9.H17(DVDD33_USB)
DVDD_DDRPLL1: C211.1 C214.1 C215.1 L12.3(OUT) U9.W8(DVDD_DDRDLL) U9.W10(DVDD_DDRDLL) U9.W14(DVDD_DDRDLL)
GND_OSC0: C45.2 C46.2 R52.1(P1) U9.AD19(VSS_OSC_SYS)
V1_8_VDDAHV: C262.1 C276.1 C277.1 L15.3(OUT) U9.K7(VDDAHV)
V5_0: C9.1 C35.1 C36.1 C120.1 C124.1 C160.1 C181.1 C202.1 FB6.2 L6.2 R10.2(P2) R13.2(P2) U5.A1(VIN1_1) U5.B1(VIN1_2) U5.C1(VIN1_3) U5.D1(VIN2_1) U5.E1(VIN2_2) U5.F1(VIN2_3) U27.1(EN) U27.8(VIN) U30.8(VIN) U35.8(VIN) ; also on sheet 24
V5_FILT: C121.1 D11.1(CATHODE) L6.1 U22.8(PH)
VDD_0V9: C191.1 C426.1 L1.2 L2.2 R45.2(P2) TP14.1 U5.A4(V0) U149.5(SENSE) ; also on sheet 27
VDD_0V9_K2G: C195.1 C200.2 C225.1 C226.2 C228.1 C230.1 C231.1 C235.2 C236.1 C239.1 C240.1 C243.1 C248.1 C249.1 C250.1 C251.1 C252.1 C253.1 C254.1 C255.1 C261.1 C263.1 C267.1 C268.1 C269.1 C272.1 C273.1 C275.1 C428.2 U9.J10(CVDD) U9.J12(CVDD1) U9.J14(CVDD) U9.J16(CVDD) U9.K9(CVDD) U9.K11(CVDD) U9.K13(CVDD) U9.K15(CVDD) U9.K17(CVDD) U9.L10(CVDD) U9.L12(CVDD) U9.L14(CVDD) U9.L16(CVDD) U9.L18(CVDD) U9.M5(CVDD1) U9.M9(CVDD) U9.M11(CVDD) U9.M13(CVDD) U9.M15(CVDD) U9.M17(CVDD) U9.N8(CVDD1) U9.N10(CVDD) U9.N12(CVDD) U9.N14(CVDD) U9.N16(CVDD) U9.N18(CVDD1) U9.P9(CVDD) U9.P11(CVDD) U9.P13(CVDD) U9.P15(CVDD) U9.P17(CVDD) U9.R8(CVDD) U9.R10(CVDD) U9.R12(CVDD) U9.R14(CVDD) U9.R16(CVDD) U9.R18(CVDD) U9.T9(CVDD) U9.T11(CVDD) U9.T13(CVDD1) U9.T15(CVDD) U9.T17(CVDD) U9.U16(CVDD) ; also on sheet 27
VDD_1V8: C209.1 L11.2 R67.1(P1) R330.2(P2) TP17.1 U35.5(VOS) ; also on sheet 13 18 26 27
VDD_1V8_K2G: C217.1 C218.1 C222.1 C223.1 C245.1 C259.1 C264.1 C265.1 C266.1 C270.1 C274.1 C291.1 L3.1(IN) L4.1(IN) L5.1(IN) L10.1(IN) L12.1(IN) L14.1(IN) L15.1(IN) L16.1(IN) L17.1(IN) L18.1(IN) R367.2(P2) R372.2(P2) U9.F17(DVDD18) U9.J6(DVDD18) U9.K19(DVDD18) U9.L6(DVDD18) U9.L20(DVDD18) U9.M7(DVDD18) U9.U6(DVDD18) U9.U18(DVDD18) U9.V19(DVDD18) U9.W6(DVDD18) ; also on sheet 27
VDD_3V3: C132.1 C194.1 C353.1 C380.1 C381.1 C425.2 L8.2 R30.1(P1) R55.2(P2) R63.2(P2) R65.2(P2) R68.2(P2) R69.1(P1) R70.2(P2) R71.1(P1) R72.2(P2) R73.1(P1) R74.2(P2) R76.2(P2) R252.2(P2) R260.2(P2) R281.2(P2) R322.2(P2) R323.2(P2) R325.1(P1) R331.2(P2) R333.2(P2) R339.2(P2) R340.2(P2) R341.2(P2) R342.2(P2) R344.2(P2) R346.2(P2) R347.2(P2) R350.2(P2) R373.1 R469.2 R501.1(P1) R504.1(P1) R505.2(P2) R525.2(P2) R527.1 R548.2(P2) R549.2(P2) R556.1(P1) R557.2(P2) TP5.1 U21.6(AVIN) U27.5(VOS) U52.8(VCC) U149.6(VDD) U150.5(VCC) ; also on sheet 12 13 14 15 16 17 18 19 20 21 22 23 24 25 26 27
VDD_3V3_K2G: C210.1 C224.1 C227.1 C229.1 C232.1 C233.1 C234.1 C237.1 C238.1 C241.1 C271.1 C278.1 C279.1 C280.1 C281.1 C282.1 C284.1 C286.1 C288.1 C289.1 C290.1 C295.1 C297.1 C299.1 C300.1 R378.2(P2) U9.AA23(DVDD33) U9.E23(DVDD33) U9.F7(DVDD33) U9.F11(DVDD33) U9.F15(DVDD33) U9.F21(DVDD33) U9.G12(DVDD33) U9.G16(DVDD33) U9.G20(DVDD33) U9.H9(DVDD33) U9.H11(DVDD33) U9.H13(DVDD33) U9.H15(DVDD33) U9.J20(DVDD33) U9.P7(DVDD33) U9.P19(DVDD33) U9.R6(DVDD33) U9.R20(DVDD33) U9.T7(DVDD33) U9.T19(DVDD33) U9.T23(DVDD33) U9.U20(DVDD33) U9.V21(DVDD33) ; also on sheet 27
VDD_LED: C310.1 D14.1(A) D15.1(A) D17.1(A) D18.1(A) FB6.1 R237.2(P2)
VDDA18_BAW: C292.1 C293.1 C294.1 L16.3(OUT) U9.H5(DVDD18)
VDDS_DDR: C157.1 L9.2 R293.1(P1) R294.2(P2) TP4.1 U30.5(VOS) ; also on sheet 27
VDDS_DDR_K2G: C10.2 C11.2 C12.2 C19.1 C24.2 C27.2 C33.2 C38.1 C47.1 C113.1 C125.2 C126.2 C127.2 C128.1 C131.1 C133.1 C136.1 C137.1 C138.2 C139.1 C140.1 C141.2 C142.1 C143.1 C144.1 C145.1 C146.1 C147.1 C148.1 C149.1 C150.1 C151.1 C153.1 C154.1 C155.1 C156.2 C158.1 C163.2 C164.1 C165.1 C166.1 C167.1 C168.1 C170.1 C171.1 C172.1 C173.1 C174.1 C175.1 C177.1 C179.1 C180.1 C182.1 C183.1 C184.1 C185.1 C190.1 C196.1 C201.1 C203.1 C204.1 C205.1 C206.1 C207.1 C213.1 C216.1 C219.1 R550.2(P2) R552.2(P2) U4.A1(VDDQ) U4.A8(VDDQ) U4.B2(VDD) U4.C1(VDDQ) U4.C9(VDDQ) U4.D2(VDDQ) U4.D9(VDD) U4.E9(VDDQ) U4.F1(VDDQ) U4.G7(VDD) U4.H2(VDDQ) U4.H9(VDDQ) U4.K2(VDD) U4.K8(VDD) U4.N1(VDD) U4.N9(VDD) U4.R1(VDD) U4.R9(VDD) U9.AD5(DVDD_DDR) U9.AD11(DVDD_DDR) U9.AD18(DVDD_DDR) U9.AE8(DVDD_DDR) U9.AE14(DVDD_DDR) U9.U8(DVDD_DDR) U9.U10(DVDD_DDR) U9.U12(DVDD_DDR) U9.U14(DVDD_DDR) U9.V7(DVDD_DDR) U9.V11(DVDD_DDR) U9.V13(DVDD_DDR) U9.V15(DVDD_DDR) U9.V17(DVDD_DDR) U9.W16(DVDD_DDR) U9.W18(DVDD_DDR) U21.5(VDDQ) U21.7(PVIN) ; also on sheet 27
VDDSDDR_SW: L9.1 U30.7(SW)
A_ARMPLL: C48.1 C51.1 C247.1 L4.3(OUT) U9.N6(AVDDA_ARMPLL)
A_DDRPLL: C208.1 C220.1 C221.1 L10.3(OUT) U9.W20(AVDDA_DDRPLL)
A_ICSSPLL: C287.1 C298.1 C302.1 L18.3(OUT) U9.G8(AVDDA_ICSSPLL)
A_NSSPLL: C53.1 C58.1 C283.1 L5.3(OUT) U9.G14(AVDDA_NSSPLL)
A_UARTPLL: C285.1 C296.1 C301.1 L17.3(OUT) U9.G10(AVDDA_UARTPLL)
BOOTCMPLT: Q12.1(G) R501.2(P2) U9.Y3(BOOTCOMPLETE)
BOOTMODE3: R75.2(P2) SW1.4 U9.N24(DSS_DATA20)
BOOTMODE4: R332.2(P2) SW2.1 U9.T25(DSS_DATA19)
BOOTMODE5: R55.1(P1) R56.2(P2) U9.N22(DSS_DATA18)
BOOTMODE6: R338.2(P2) SW2.2 U9.R24(DSS_DATA17)
BOOTMODE7: R349.2(P2) SW2.3 U9.P23(DSS_DATA16)
BOOTMODE8: R72.1(P1) R351.2(P2) U9.R22(DSS_DATA15)
BOOTMODE9: R352.2(P2) SW2.4 U9.U25(DSS_DATA14)
BOOTMODE10: R76.1(P1) R354.2(P2) U9.P21(DSS_DATA13)
BOOTMODE15: R335.2(P2) R342.1(P1) U9.T22(DSS_DATA8)
CLKSEL: R356.2(P2) R558.2(P2) U9.L2(RSV6)
DDR3_A0: R269.2(P2) U4.N3(A0) U9.AC15(DDR3_A00)
DDR3_A1: R289.2(P2) U4.P7(A1) U9.Y15(DDR3_A01)
DDR3_A2: R20.2(P2) U4.P3(A2) U9.AC16(DDR3_A02)
DDR3_A3: R23.2(P2) U4.N2(A3) U9.AA15(DDR3_A03)
DDR3_A4: R292.2(P2) U4.P8(A4) U9.AB16(DDR3_A04)
DDR3_A5: R21.2(P2) U4.P2(A5) U9.AE17(DDR3_A05)
DDR3_A6: R299.2(P2) U4.R8(A6) U9.AC14(DDR3_A06)
DDR3_A7: R32.2(P2) U4.R2(A7) U9.AB15(DDR3_A07)
DDR3_A8: R300.2(P2) U4.T8(A8) U9.AC17(DDR3_A08)
DDR3_A9: R36.2(P2) U4.R3(A9) U9.AB17(DDR3_A09)
DDR3_A10: R24.2(P2) U4.L7(A10/AP) U9.AB14(DDR3_A10)
DDR3_A11: R40.2(P2) U4.R7(A11) U9.AA16(DDR3_A11)
DDR3_A12: R22.2(P2) U4.N7(A12/~{BC}) U9.AA17(DDR3_A12)
DDR3_A13: R37.2(P2) U4.T3(A13) U9.AA12(DDR3_A13)
DDR3_A14: R41.2(P2) U4.T7(A14) U9.Y17(DDR3_A14)
DDR3_BA0: R25.2(P2) U4.M2(BA0) U9.AA14(DDR3_BA0)
DDR3_BA1: R298.2(P2) U4.N8(BA1) U9.AB13(DDR3_BA1)
DDR3_BA2: R268.2(P2) U4.M3(BA2) U9.AD17(DDR3_BA2)
DDR3_CASN: R266.2(P2) U4.K3(CASn) U9.AC13(DDR3_CASn)
DDR3_CKE: R39.2(P2) U4.K9(CKE) U9.AB18(DDR3_CKE0)
DDR3_CLK0: R264.2(P2) U4.J7(CK) U9.AE15(DDR3_CLKOUT_P0)
DDR3_CLK0N: R265.2(P2) U4.K7(CKn) U9.AD15(DDR3_CLKOUT_N0)
DDR3_CLK_TERM: C128.2 R264.1(P1) R265.1(P1)
DDR3_CSN0: R27.2(P2) U4.L2(CSn) U9.AD13(DDR3_CEn0)
DDR3_D0: U4.E3(DQ0) U9.AD2(DDR3_D00)
DDR3_D1: U4.H3(DQ4) U9.Y4(DDR3_D01)
DDR3_D2: U4.H8(DQ5) U9.AC3(DDR3_D02)
DDR3_D3: U4.F2(DQ2) U9.AC2(DDR3_D03)
DDR3_D4: U4.F7(DQ1) U9.AE3(DDR3_D04)
DDR3_D5: U4.G2(DQ6) U9.AA4(DDR3_D05)
DDR3_D6: U4.F8(DQ3) U9.AD3(DDR3_D06)
DDR3_D7: U4.H7(DQ7) U9.AB3(DDR3_D07)
DDR3_D8: U4.D7(DQ8) U9.AA6(DDR3_D08)
DDR3_D9: U4.C3(DQ9) U9.Y7(DDR3_D09)
DDR3_D10: U4.C2(DQ11) U9.Y6(DDR3_D10)
DDR3_D11: U4.A7(DQ12) U9.AC5(DDR3_D11)
DDR3_D12: U4.C8(DQ10) U9.AB6(DDR3_D12)
DDR3_D13: U4.A2(DQ13) U9.Y5(DDR3_D13)
DDR3_D14: U4.B8(DQ14) U9.AC4(DDR3_D14)
DDR3_D15: U4.A3(DQ15) U9.AB5(DDR3_D15)
DDR3_DQM0: U4.E7(LDM) U9.AB4(DDR3_DQM0)
DDR3_DQM1: U4.D3(UDM) U9.AA5(DDR3_DQM1)
DDR3_DQS0: U4.F3(LDQS) U9.AD1(DDR3_DQS0_P)
DDR3_DQS1: U4.C7(UDQS) U9.AD4(DDR3_DQS1_P)
DDR3_DQSN0: U4.G3(LDQSn) U9.AE2(DDR3_DQS0_N)
DDR3_DQSN1: U4.B7(UDQSn) U9.AE4(DDR3_DQS1_N)
DDR3_ODT0: R28.2(P2) U4.K1(ODT) U9.AA13(DDR3_ODT0)
DDR3_RASN: R26.2(P2) U4.J3(RASn) U9.AE13(DDR3_RASn)
DDR3_RST: R42.2 TP12.1 U4.T2(RESETn) U9.Y18(DDR3_RESETn)
DDR3_WEN: R267.2(P2) U4.L3(WEn) U9.Y13(DDR3_WEn)
DDR_VTT_SDn: R251.2(P2) R252.1(P1) U21.2(SDn) ; also on sheet 24
EEWP: R469.1 U52.7(WP)
EMU2: R327.2(P2) SW1.1 U9.N23(DSS_DATA23/EMU02) ; also on sheet 19
EMU3: R57.2(P2) SW1.2 U9.P25(DSS_DATA22/EMU03) ; also on sheet 19
EMU4: R58.2(P2) SW1.3 U9.P24(DSS_DATA21/EMU04) ; also on sheet 19
eQEP2_A: U9.U23(DSS_DATA4/eQEP2_A) ; also on sheet 24
eQEP2_B: U9.V23(DSS_DATA3/eQEP2_B) ; also on sheet 24
eQEP2_I: U9.W22(DSS_DATA2/eQEP2_I) ; also on sheet 24
eQEP2_S: U9.U21(DSS_DATA1/eQEP2_S) ; also on sheet 24
I2C_SCL0: R346.1(P1) U9.U5(I2C0_SCL) U52.6(SCL) ; also on sheet 13 24
I2C_SCL1: R323.1(P1) U9.V6(I2C1_SCL) ; also on sheet 19 20 25
I2C_SCL2: R548.1(P1) U9.V5(I2C2_SCL) ; also on sheet 27
I2C_SDA0: R344.1(P1) U9.W5(I2C0_SDA) U52.5(SDA) ; also on sheet 13 24
I2C_SDA1: R322.1(P1) U9.W4(I2C1_SDA) ; also on sheet 19 20 25
I2C_SDA2: R549.1(P1) U9.V4(I2C2_SDA) ; also on sheet 27
K2G_OSC0_IN: C45.1 R53.2(P2) U9.AC19(SYSOSC_IN) Y1.3
K2G_OSC0_OUT: R54.1(P1) U9.AE19(SYSOSC_OUT)
K2G_PORZn: R328.1(P1) U9.AA3(PORn)
LED_1: Q6.5 R454.2(P2) ; also on sheet 24
LED_2: Q4.2(5) R435.2(P2) ; also on sheet 24
LED_3: Q4.5 R431.2(P2) ; also on sheet 24
LED_4: Q5.2(5) R448.2(P2) TP33.1 ; also on sheet 24
LED_5: Q5.5 R455.2(P2) ; also on sheet 24
LED_6: Q6.2(5) R441.2(P2) ; also on sheet 24
LED_7: R458.2(P2) ; also on sheet 24
LED_8: Q1.5 R74.1(P1) R353.2(P2) R388.2(P2) U9.R21(DSS_DATA9/GPIO0_44)
LED_9: Q1.2(5) R65.1(P1) R343.2(P2) R401.2(P2) U9.U24(DSS_DATA10/GPIO0_43)
LED_10: Q3.5 R63.1(P1) R337.2(P2) R426.2(P2) U9.V25(DSS_DATA11/GPIO0_42)
LED_11: Q2.5 R70.1(P1) R348.2(P2) R422.2(P2) TP26.1 U9.T24(DSS_DATA12/GPIO0_41)
LED_12: Q2.2(5) R429.2(P2) ; also on sheet 26
LED_13: Q3.2(5) R412.2(P2) ; also on sheet 26
LRESETNMIENZ: R71.2(P2) U9.V1(LRESETNMIENn) U9.V2(LRESETn) U9.W1(NMIn)
OSC0_OUT: C46.1 R53.1(P1) R54.2(P2) Y1.1
PERST: U150.2(B) ; also on sheet 25
PGOOD_0.9V: R527.2 U5.F4(PG)
PGOOD_1V8: R67.2(P2) U30.1(EN) U35.6(PG)
PGOOD_1V35: R293.2(P2) U5.E4(EN) U30.6(PG)
PGOOD_3V3: R30.2(P2) U27.6(PG) U35.1(EN)
PORZn: R328.2(P2) TP23.1 U150.4(Y) ; also on sheet 12
PR0_EDIO_OUTVALID: U9.L25(DSS_FID/PR0_EDIO_OUTVALID) ; also on sheet 24
PR1_ECAP0_ECAP_CAPIN_APWM_O: U9.R25(DSS_VSYNC/PR1_eCAP0_eCAP_CAPIN_APWM_O) ; also on sheet 24
PR1_ECAP0_ECAP_SYNCIN: U9.P22(DSS_HSYNC/PR1_eCAP0_eCAP_SYNCIN) ; also on sheet 24
PR1_ECAP0_ECAP_SYNCOUT: U9.N25(DSS_PCLK/PR1_eCAP0_eCAP_SYNCOUT) ; also on sheet 24
RESETFULLZ: R69.2(P2) U9.W2(RESETFULLn)
RESETSTATZ: Q11.1(G) R504.2(P2) U9.Y2(RESETSTATn) ; also on sheet 12 13 14 15 16 17
RESETZ: R326.1(P1) U9.W3(RESETn)
SPIMEM_RST: U9.U22(DSS_DATA7/GPIO0_46) ; also on sheet 12
SYS_RESETn: R309.1(P1) ; also on sheet 19
SYS_WARMRESETn: R309.2(P2) R325.2(P2) R326.2(P2) TP10.1 ; also on sheet 21
SYSCLKSEL: J3.1 R73.2(P2) U9.R1(SYSCLKSEL)
VMAIN: C16.1 C17.1 C135.1 R29.2(P2) U22.2(VIN) ; also on sheet 24 28
VPP: U9.Y21(VPP)
VPP2: U9.W21(VPP2)
VREF_DDR: C115.1 C138.1 C176.1 C212.1 TP3.1 U4.H1(VREFDQ) U4.M8(VREFCA) U9.Y9(DDR3_VREFSSTL) U21.4(VREF)
VSENSE_54531: C7.2 R12.1(P1) R14.2(P2) U22.5(VSNS)
VTT_DDR: C10.1 C11.1 C12.1 C24.1 C27.1 C33.1 C106.1 C125.1 C126.1 C127.1 C141.1 C156.1 C163.1 R20.1(P1) R21.1(P1) R22.1(P1) R23.1(P1) R24.1(P1) R25.1(P1) R26.1(P1) R27.1(P1) R28.1(P1) R32.1(P1) R36.1(P1) R37.1(P1) R39.1(P1) R40.1(P1) R41.1(P1) R266.1(P1) R267.1(P1) R268.1(P1) R269.1(P1) R289.1(P1) R292.1(P1) R298.1(P1) R299.1(P1) R300.1(P1) U21.3(VSENSE) U21.8(VTT)
ZQ0_LO: R43.2 U4.L8(ZQ)
N28554546: D17.2(R) R208.2(P2)
N28554605: Q4.3 R453.1(P1)
N28554613: D17.3(G) R192.2(P2)
N28554617: D17.4(Y) R453.2(P2)
N28559145: D18.2(R) R235.2(P2)
N28559147: D18.4(Y) R457.2(P2)
N28559250: D18.3(G) R209.2(P2)
N28559254: Q5.6(3) R235.1(P1)
N28559256: Q6.6(3) R457.1(P1)
N28559577: D19.1(Cathode) Q7.6(3)
N28559579: D19.2(Anode) R237.1(P1)
N28559581: Q7.2(5) R458.1(P1) R460.2(P2)
N30078340: C303.1 C307.1 U9.H19(LDO_USB_CAP) U9.J18(LDO_USB_CAP)
N30096857: C197.1 C198.1 U9.J8(LDO_PCIE_CAP) U9.L8(LDO_PCIE_CAP)
N30253845: L8.1 U27.7(SW)
N30253852: R281.1(P1) R282.2(P2) U27.4(FB)
N30256335: C7.1 R12.2(P2) R13.1(P1)
N30257889: C112.1 C114.1 U22.6(COMP)
N30257937: C114.2 R253.2(P2)
N30262250: C121.2 U22.1(BOOT)
N30262779: R17.2(P2) R29.1(P1) U22.3(ENA)
N30262791: C130.1 U22.4(SS)
N30278551: R294.1(P1) R295.2(P2) U30.4(FB)
N30280601: L2.1 U5.A2(SW1_1) U5.B2(SW1_2) U5.C2(SW1_3)
N30280607: L1.1 U5.D2(SW2_1) U5.E2(SW2_2) U5.F2(SW2_3)
N30281370: C40.1 U5.D4(SS/TR)
N30281511: R45.1(P1) R46.2(P2) U5.B4(FB)
N30289755: C394.2 R373.2 SW3.3 SW3.4 U149.3(~{MR})
N30314752: L11.1 U35.7(SW)
N30314809: R324.2(P2) R330.1(P1) U35.4(FB)
N31545649: D1.2(Anode) R10.1(P1)
N31611506: R315.2 U9.W12(DDR3_RZQ0)
N31611509: R336.2 U9.V9(DDR3_RZQ1)
N31627381: D14.2(R) R147.2(P2)
N31627383: D14.4(Y) R148.2(P2)
N31627423: Q1.6(3) R111.1(P1)
N31627441: D14.3(G) R111.2(P2)
N31627556: D15.2(R) R191.2(P2)
N31627558: D15.4(Y) R432.2(P2)
N31627654: D15.3(G) R182.2(P2)
N31627658: Q2.3 R191.1(P1)
N31627660: Q3.6(3) R432.1(P1)
N31627680: Q2.6(3) R182.1(P1)
N31694634: J3.2 R47.2(P2)
N33238028: D22.1(Cathode) Q11.3(D)
N33238046: D20.1(Cathode) Q12.3(D)
N33264752: R525.1(P1) U149.1(~{RESET}) U150.1(A)
N33352019: Q5.3 R209.1(P1)
N33352039: Q6.3 R208.1(P1)
N33352137: Q4.6(3) R192.1(P1)
N33765474: Q1.3 R147.1(P1)
N33765737: Q3.3 R148.1(P1)
N33778830: R350.1(P1) SW1.5
N33778831: R341.1(P1) SW1.6
N33778832: R339.1(P1) SW1.7
N33778833: R333.1(P1) SW1.8
N33778854: R68.1(P1) SW2.5
N33778855: R347.1(P1) SW2.6
N33778856: R340.1(P1) SW2.7
N33778857: R331.1(P1) SW2.8
N33862909: R550.1(P1) U9.AE6(DDR3_DQS2_P)
N33862912: R551.1(P1) U9.AD6(DDR3_DQS2_N)
N33862915: R552.1(P1) U9.AE9(DDR3_DQS3_P)
N33862918: R553.1(P1) U9.AD9(DDR3_DQS3_N)
N33863899: R555.2(P2) U9.C17(AUDOSC_IN)
N33920693: Q15.3(COLLECTOR) R556.2(P2) R558.1(P1)
N33921010: C408.1 Q15.1(BASE) R557.1(P1)
N34454893: C427.2 U149.4(CT)
N35131759: TP18.1 U9.M21(SYSCLKOUT)
N35349649: D22.2(Anode) R260.1(P1)
N35349650: D20.2(Anode) R505.1(P1)

Not connected (* = marked no-connect by the designer): Q7 3* 4* 5*; U4 J1(NU0)* J9(NU1)* L1(NU2)* L9(NU3)* M7(NU4)*; U9 A17(AUDOSC_OUT)* AA7(DDR3_D19)* AA8(DDR3_D20)* AA9(DDR3_DQM3)* AA10(DDR3_D24)* AA11(DDR3_CB00)* AB7(DDR3_D16)* AB8(DDR3_D17)* AB9(DDR3_D30)* AB10(DDR3_D29)* AB11(DDR3_CB01)* AB12(DDR3_CEn1)* AC6(DDR3_D21)* AC7(DDR3_D18)* AC8(DDR3_DQM2)* AC9(DDR3_D28)* AC10(DDR3_D27)* AC11(DDR3_CB02)* AC12(DDR3_CB03)* AC18(DDR3_CKE1)* AD7(DDR3_D23)* AD10(DDR3_D26)* AD12(DDR3_CBDQS_N)* AD16(DDR3_CLKOUT_N1)* AD24(DDR_CLK_N)* AE7(DDR3_D22)* AE10(DDR3_D25)* AE12(DDR3_CBDQS_P)* AE16(DDR3_CLKOUT_P1)* AE24(DDR_CLK_P)* M25(DSS_DE)* T21(DSS_DATA6)* V22(DSS_DATA0)* V24(DSS_DATA5)* Y8(DDR3_D31)* Y11(DDR3_CBDQM)* Y12(DDR3_ODT1)* Y16(DDR3_A15)*; Y1 2(NC0)* 4(NC1)*

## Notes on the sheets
sheet 1
- K2G ICE EVM
- V 1.0
- - See the Hardware Implementation Document for Design Details
- - See the Hardware User Guide for Board Details
- - See the PCB Build Specification for PCB Design Details
- PAGE NO.
- SHEET NAME
- PAGE NO.
- SHEET NAME
- 1
- Title
- PRU0MII1_Ethernet 2
- 16
- 2
- Revision History
- PRU0MII1_Ethernet 3
- 17
- BLOCK DIAGRAM & I2C TREE
- MICRO SD CARD
- 3
- 18
- 4
- Power Supply1
- 19
- ROTARY SWITCH ,OLED & JTAG
- 5
- Power Supply2
- 20
- INDUSTRIAL LEDS
- USB JTAG
- 6
- SYSTEM_CLOCK ,RESET & I2C
- 21
- MUX_DEMUX1
- DDR_INTERFACE
- 22
- 7
- MUX_DEMUX2
- EEPROM & ETHERNET LEDS
- 23
- 8
- EXPANSION_HEADER
- BOOT SETTINGS
- 24
- 9
- PCIe x1 EDGE CONNECTOR
- DDR3L
- 25
- 10
- 26
- GPIOs
- DDR3L DECAPS & TERMINATIONS
- 11
- 27
- CURRENT MEASUREMENT
- 12
- QSPI FLASH
- OVER VOLTAGE PROTECTION CIRCUIT
- Gigabit Ethernet
- 28
- 13
- PRU0MII0_Ethernet 0
- HARDWARE SCHEMATICS
- 14
- 29
- 15
- PRU0MII0_Ethernet 1
sheet 2
- REVISION HISTORY
- DATE
- VER #
- DESCRIPTION OF CHANGES
- AUTHOR
- R501 DNI'd from BOOTCMPLT signal (Page 06)
- 0.1
- 10th  FEB 2017
- Part number updated for Screws H9-H12 with RoHS and REACH compliant parts (Page 29)
- Mistral Design Team
- Part number updated for Screws H13-H16 with RoHS and REACH compliant parts (Page 29)
- 0.2
- 8th  MAR 2017
- Power Cord H20 removed from Kit Content
- Mistral Design Team
- 1.0
- 8th  MAR 2017
- Baselined for Production RevD
- Mistral Design Team
sheet 3
- I2C ADDRESS TABLE
- I2C TREE
- I2C DEVICES
- 7 BIT ADDRESS
- EEPROM
- CLOCK SYNTHESIZER
- IO Expansion
    Connector
- 66AK2G02
- CAT24C256W
- CDCE937PW
- EEPROM
- 0x50
- OLED Display
- 0x3C
- I2C0
- INA Devices
- 0x40 ,0x41, 0x43, 0x44
- 4 Bit IO Expander
- 0x41
- Header
   J14
- INA Devices x4
- 8 Bit LED Driver
- 0x6x
- CLOCK SYNTHESIZER
- 0x6D
- I2C1
- OLED Display
- 4 Bit IO Expander
- 8 Bit LED Driver
- OSD9616P0992-10
- PCA9536DGK
- TPIC2810
sheet 4
- 3.3V Power Generation
- 24V - 5V Power Generation
- 2A max
- 5A max
- 1.8V Power Generation
- 2A max
- DDR3L 1.35V Power Generation
- 1.2A max
- 0.9V Power Generation
- DDR VREF & VTT Power Generation
- 5A max
- 1.5A max
- Power On Reset
- Power On LED
- GROUND PROBING POINTS
sheet 5
- K2G POWER
sheet 6
- K2G CLOCK & RESET
- SYSCLK SOURCE SELECT JUMPER
- Jumper (J3)
- CLOCK Selection
- No SHUNT
- External Clock
- Internal Clock
- SHUNT
- I2C
sheet 7
- DDR3L INTERFACE
sheet 8
- ETHERNET LEDS
- BOARD ID EEPROM
- I2C Address = 0x50h
- Green1
sheet 9
- BOOT CONFIGURATION SETTINGS
- SWITCH ON  =  LOGIC 1
  SWITCH OFF =  LOGIC 0
- BOOT MODES SUPPORTED
- 1. QSPI48
- 2. QSPI96
- 3. SD CARD
- 4. EMULATOR
- 5. PCIe
sheet 10
- DDR3L
sheet 11
- DDR3 SECTION TERMINATIONS
- DDR3 SECTION DE-CAPS
